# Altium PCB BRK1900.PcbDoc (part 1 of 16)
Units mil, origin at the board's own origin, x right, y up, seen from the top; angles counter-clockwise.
Board outline 8858.27 x 5905.51 mil, 10 copper layers (L1-TOP, L2-GND, L3-PWR, L4-GND, L5-PWR, L6-PWR, L7-GND, L8-SIG, L9-GND, L10-BOT), stack 48.824 mil thick; 456 components, 571 nets, 2296 pads, 2416 vias.
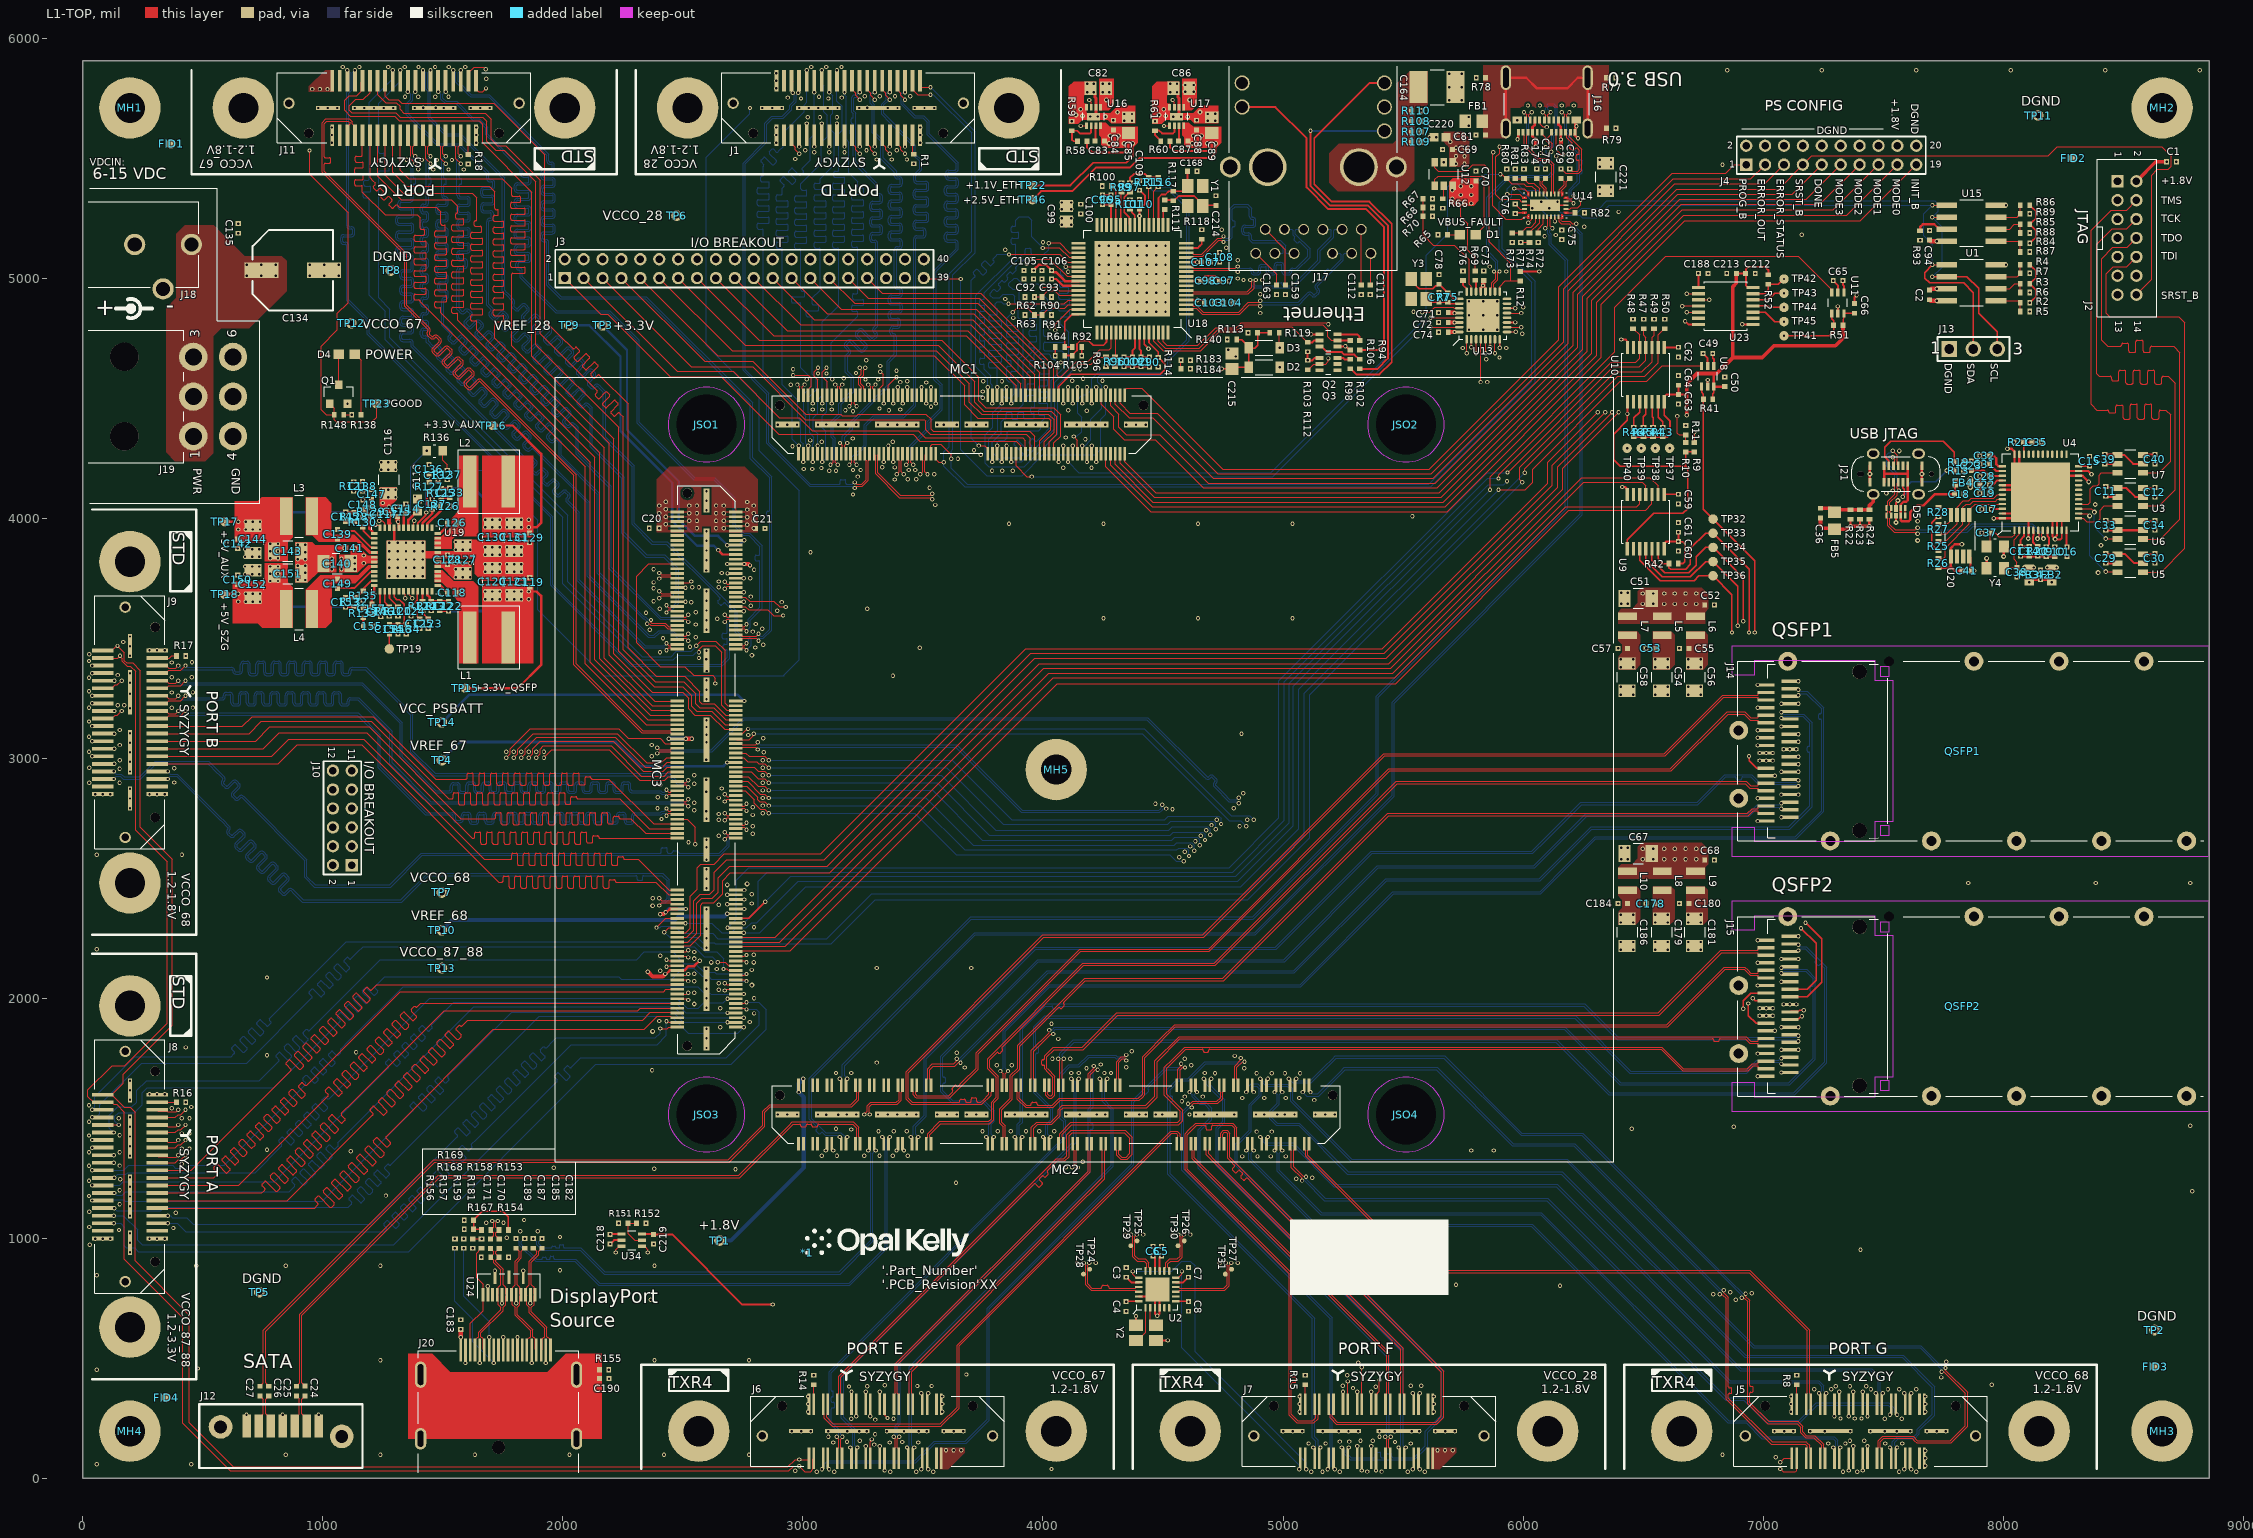
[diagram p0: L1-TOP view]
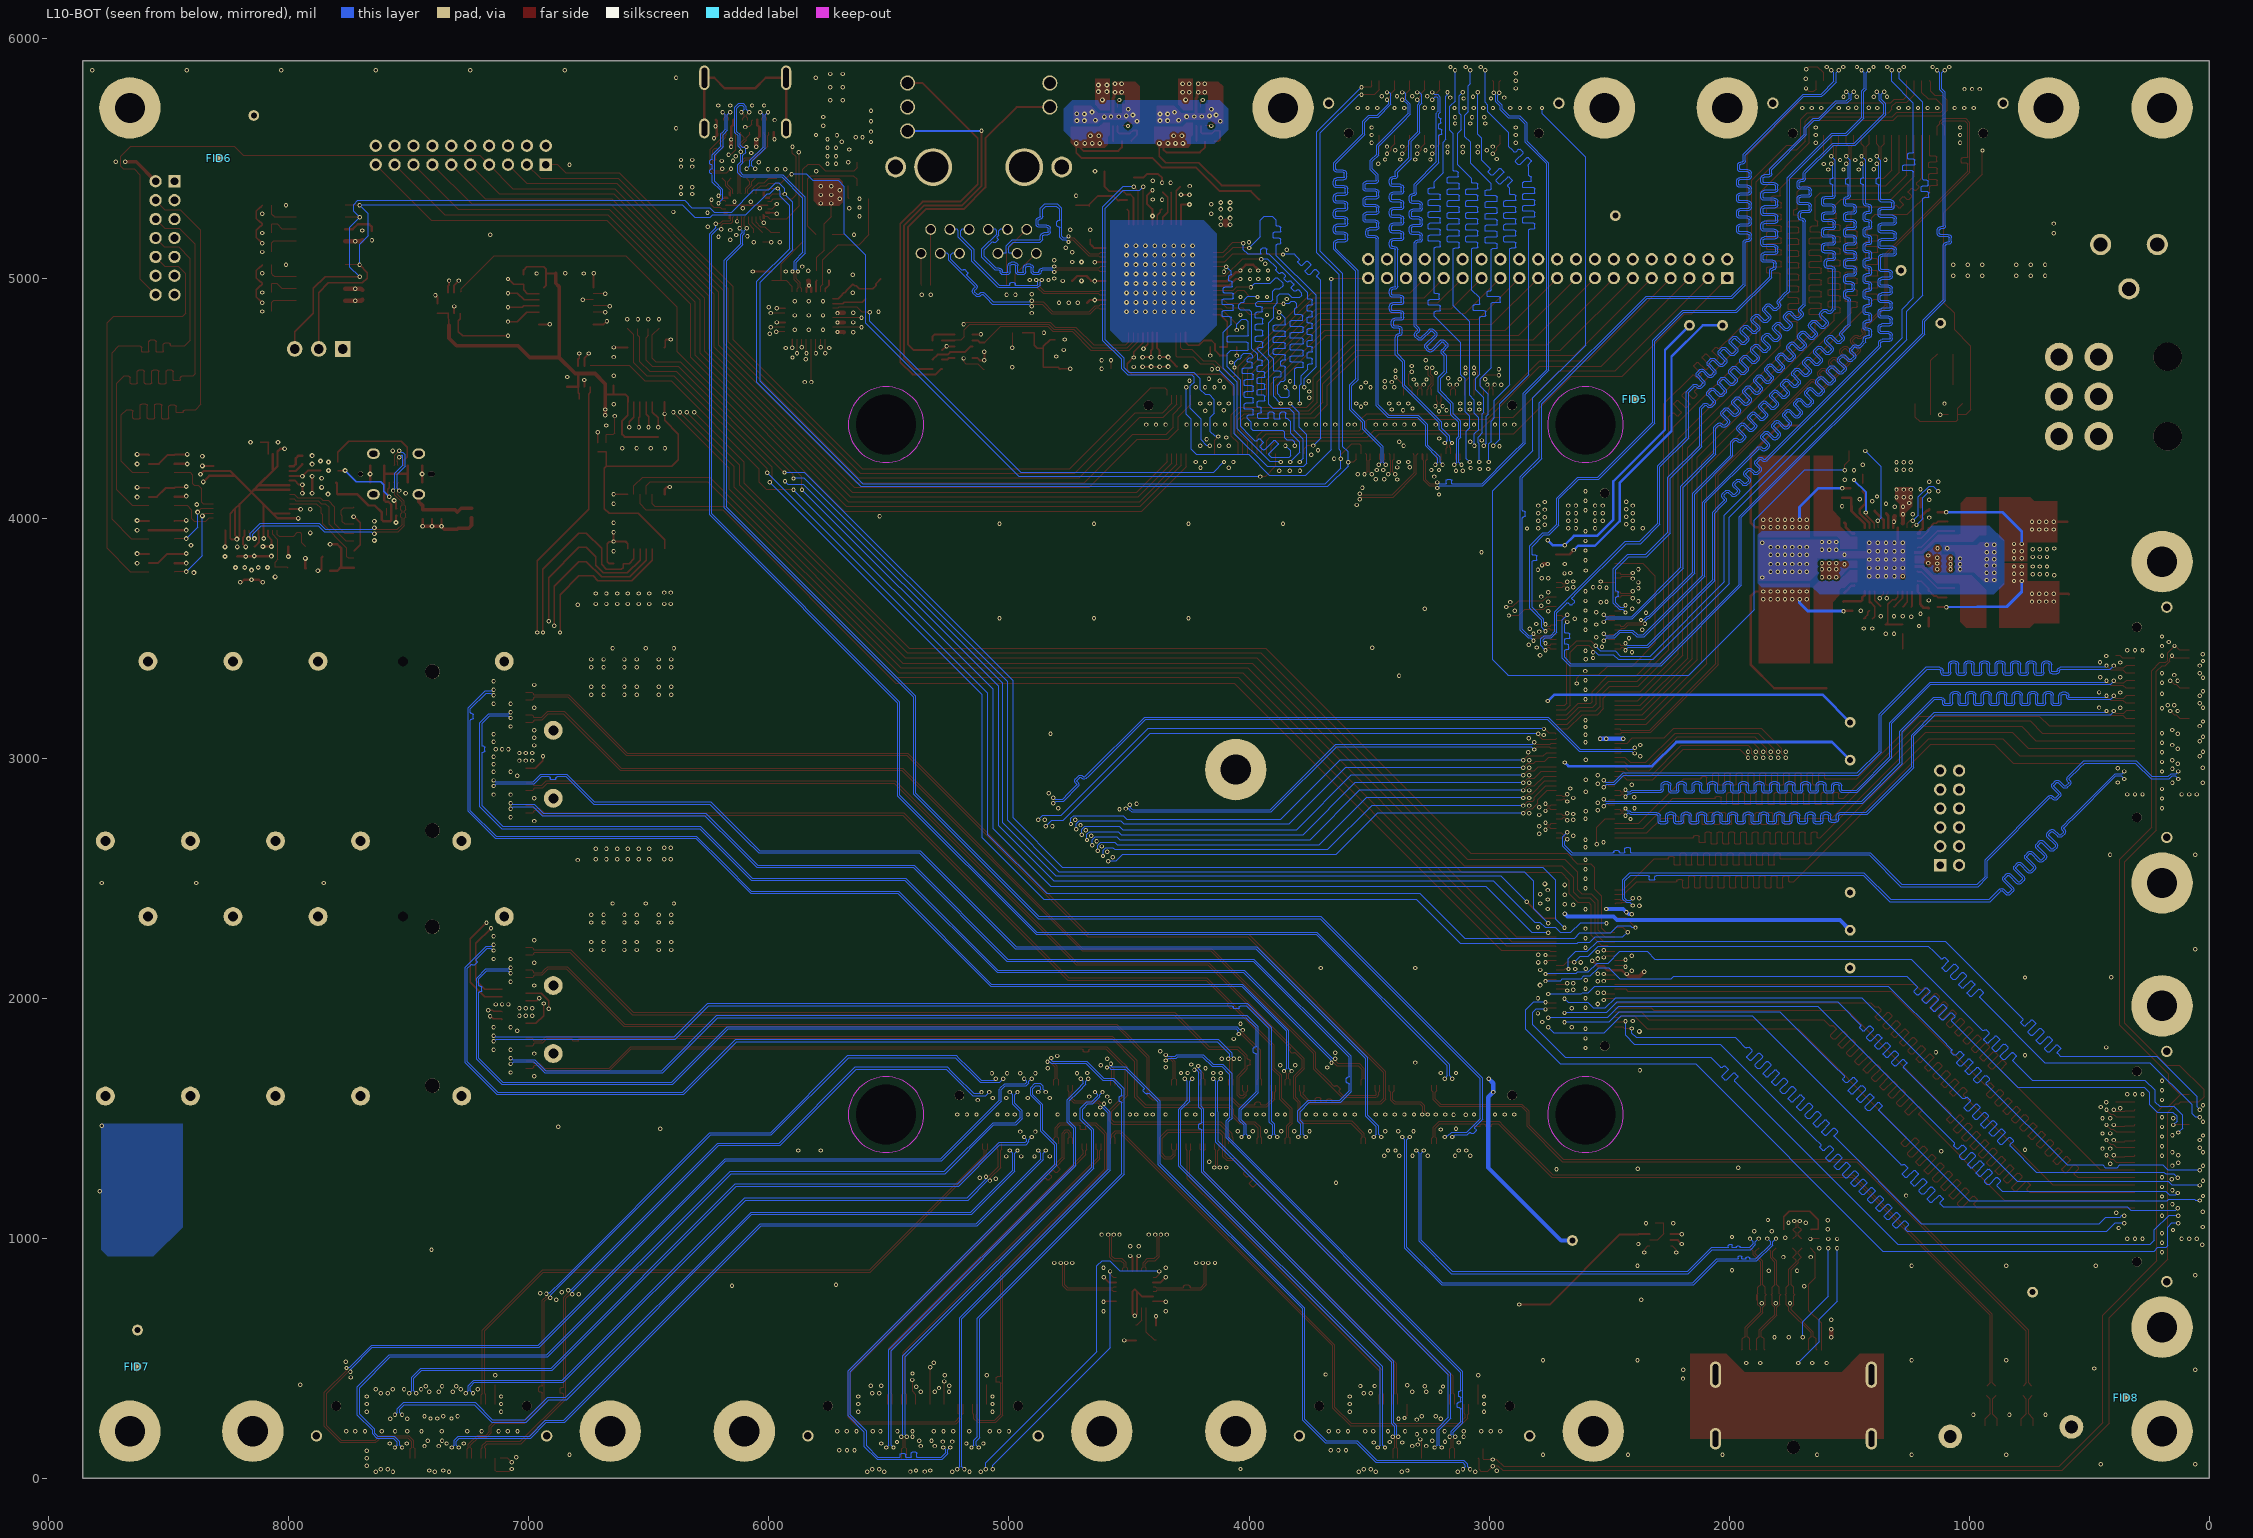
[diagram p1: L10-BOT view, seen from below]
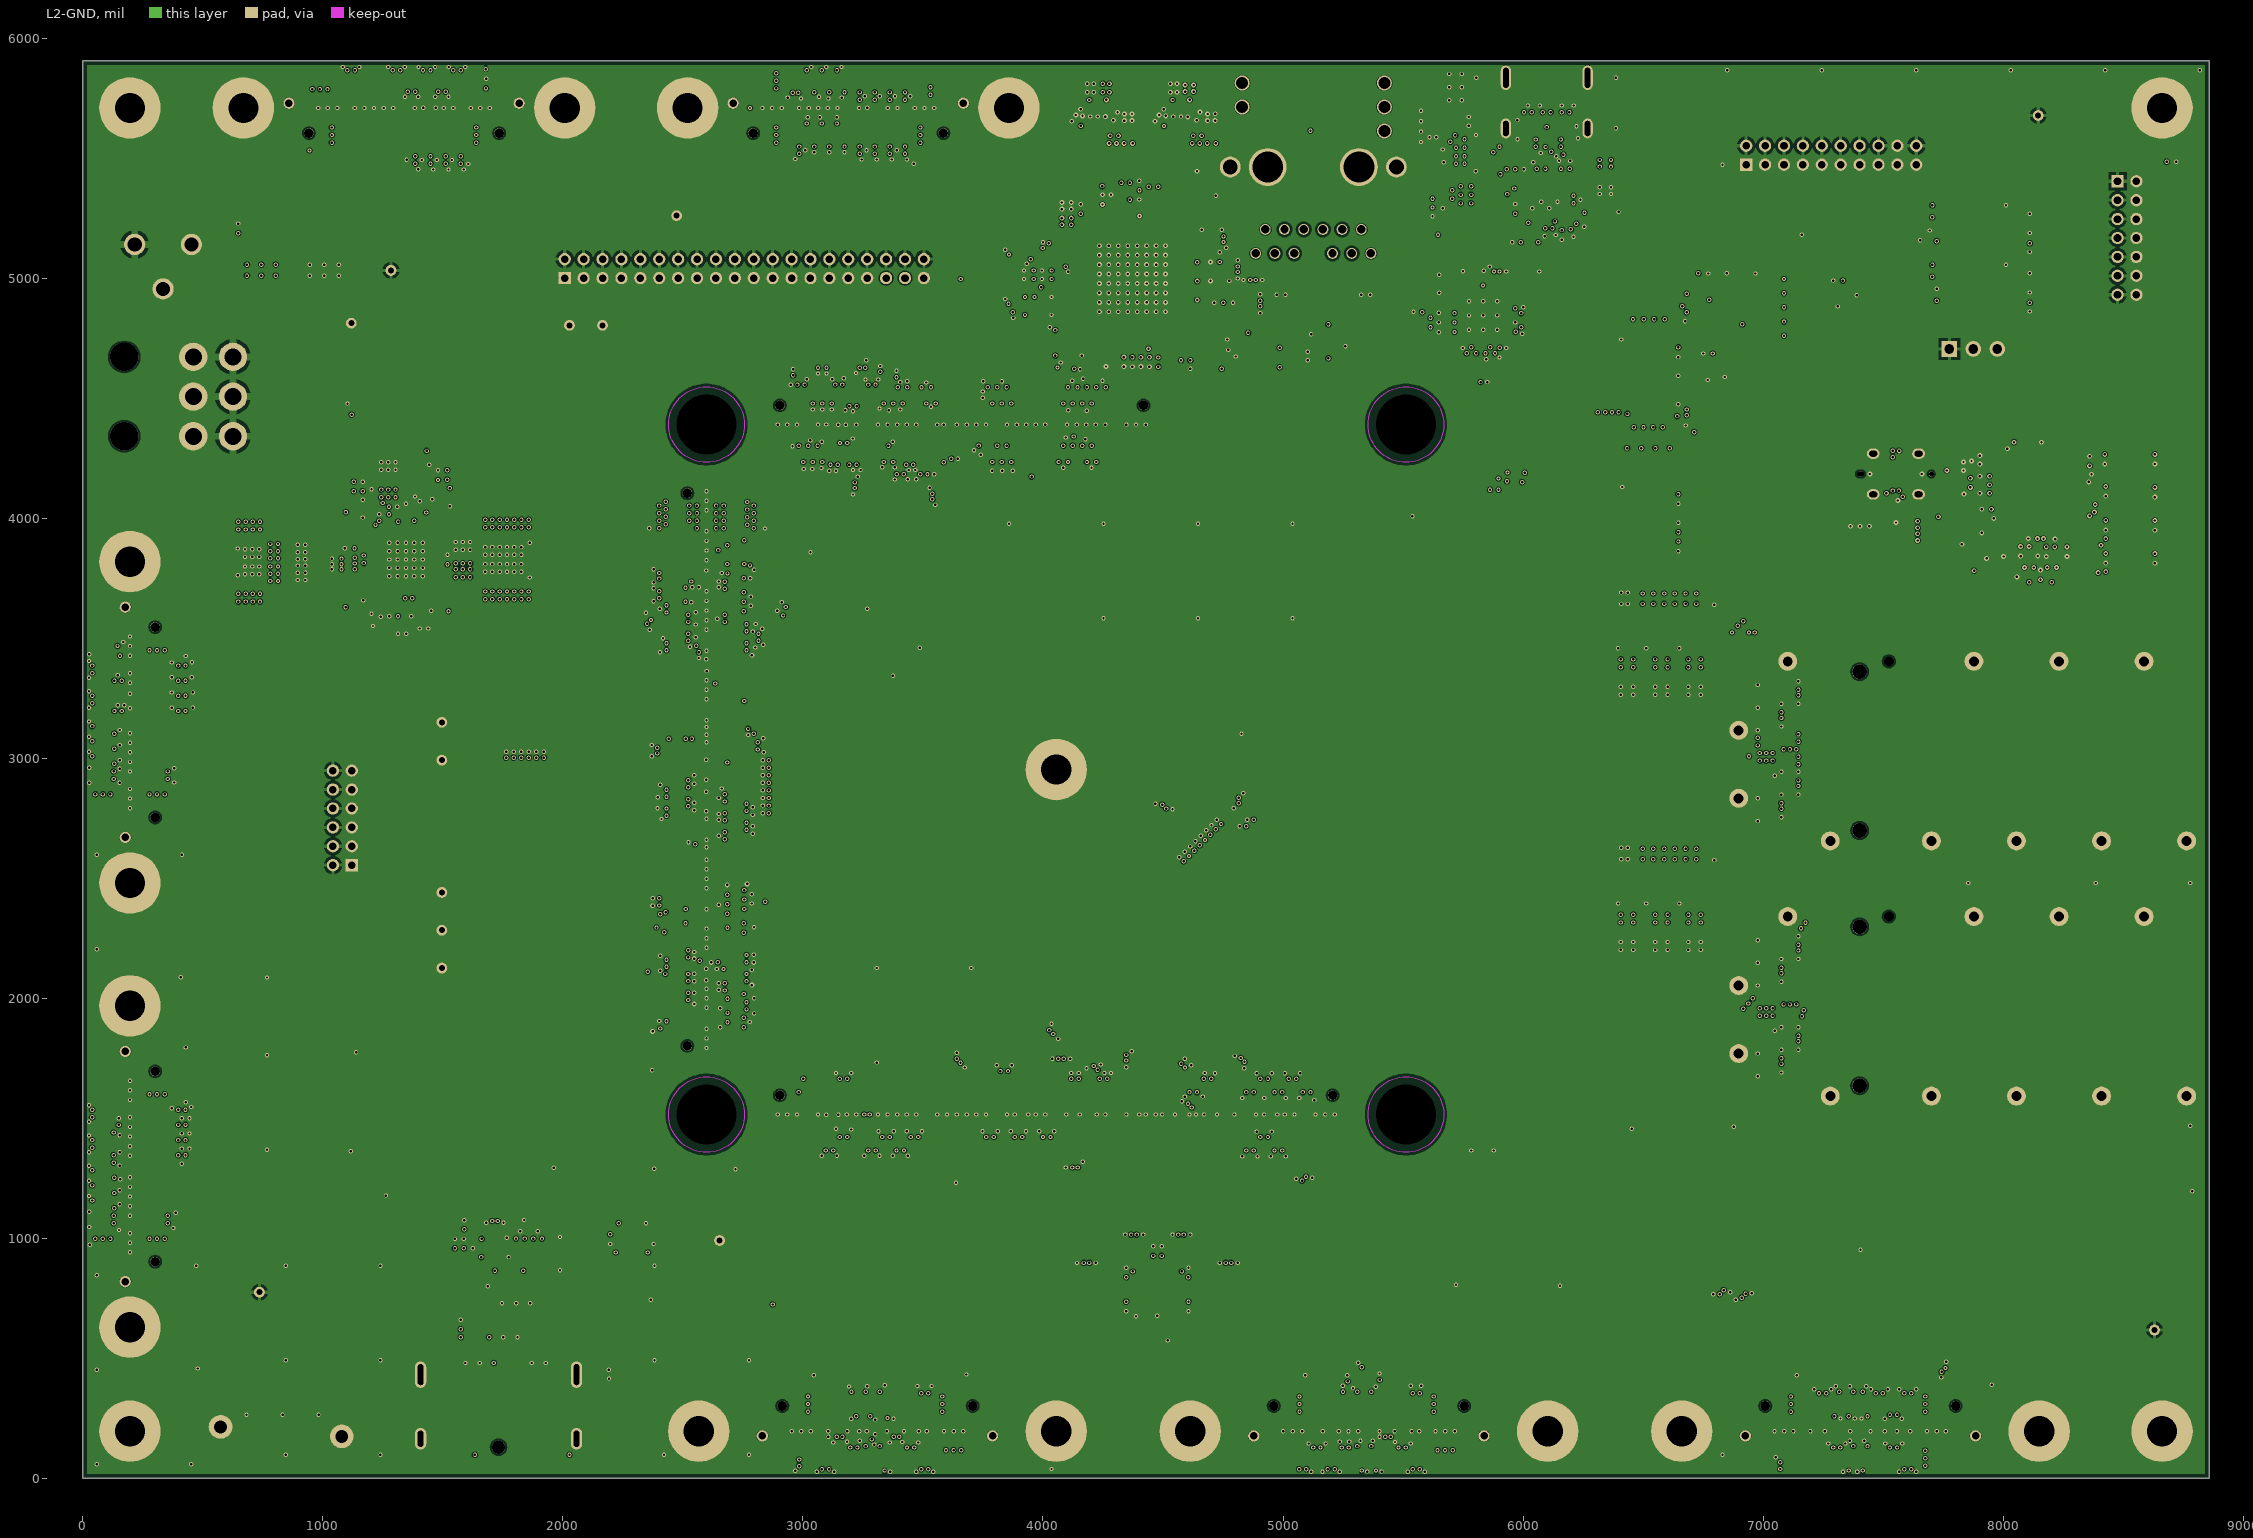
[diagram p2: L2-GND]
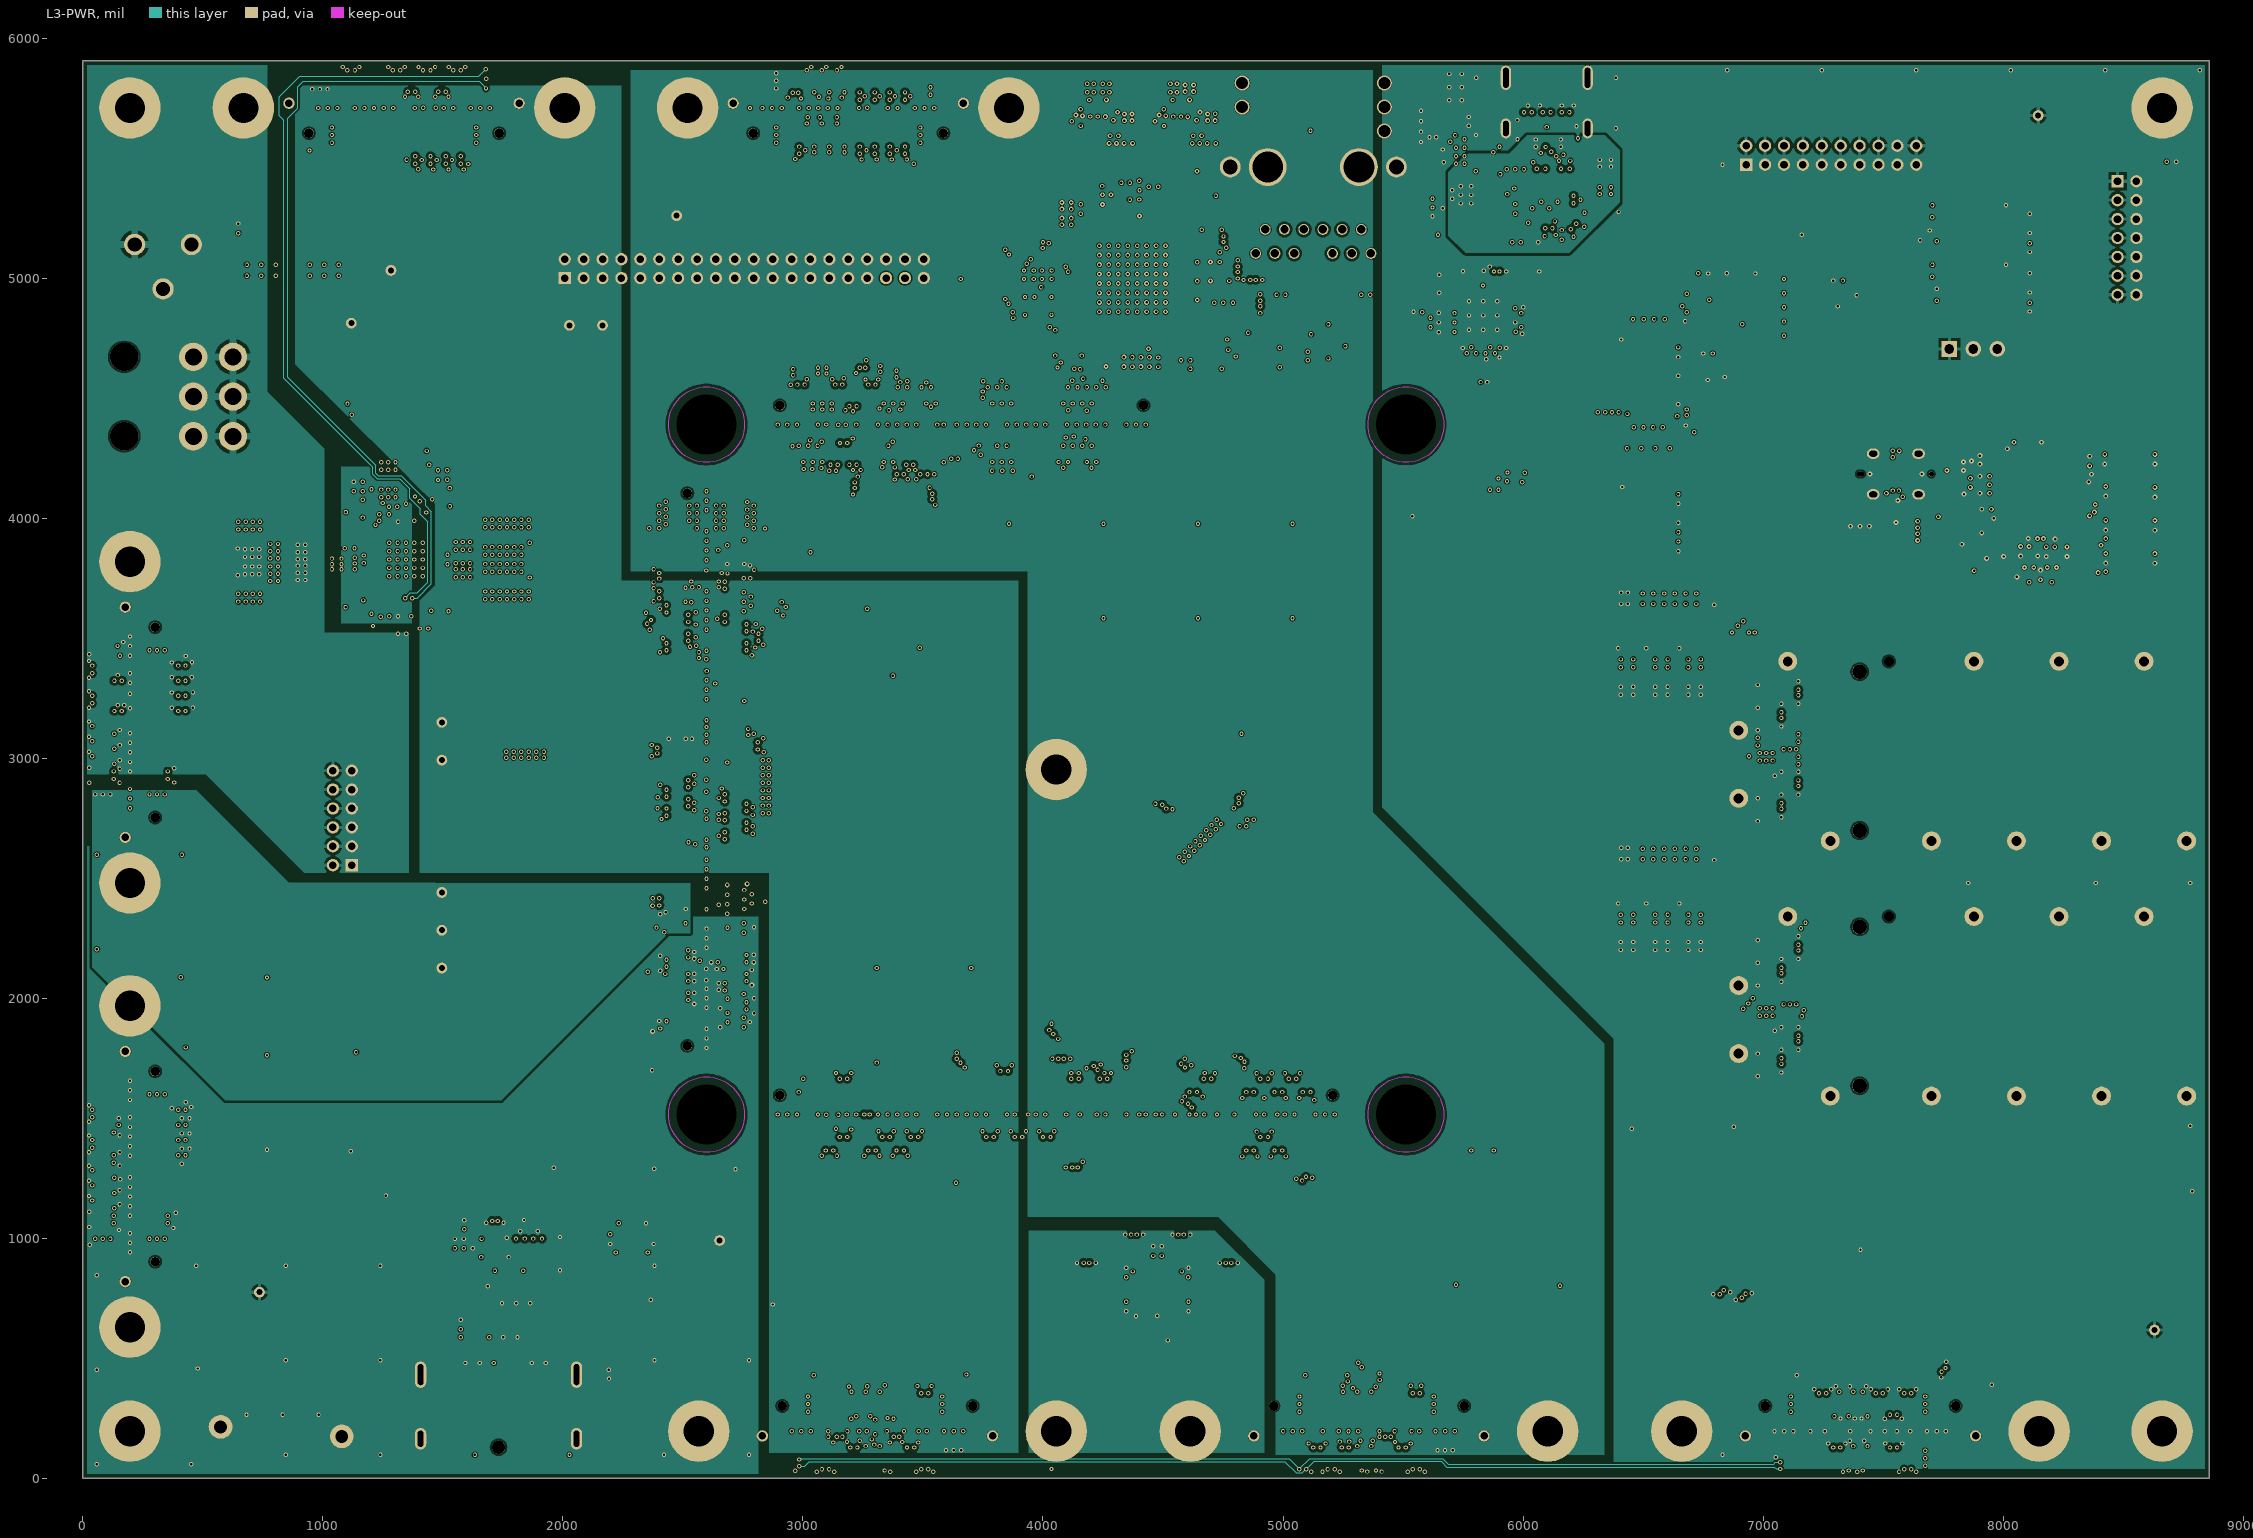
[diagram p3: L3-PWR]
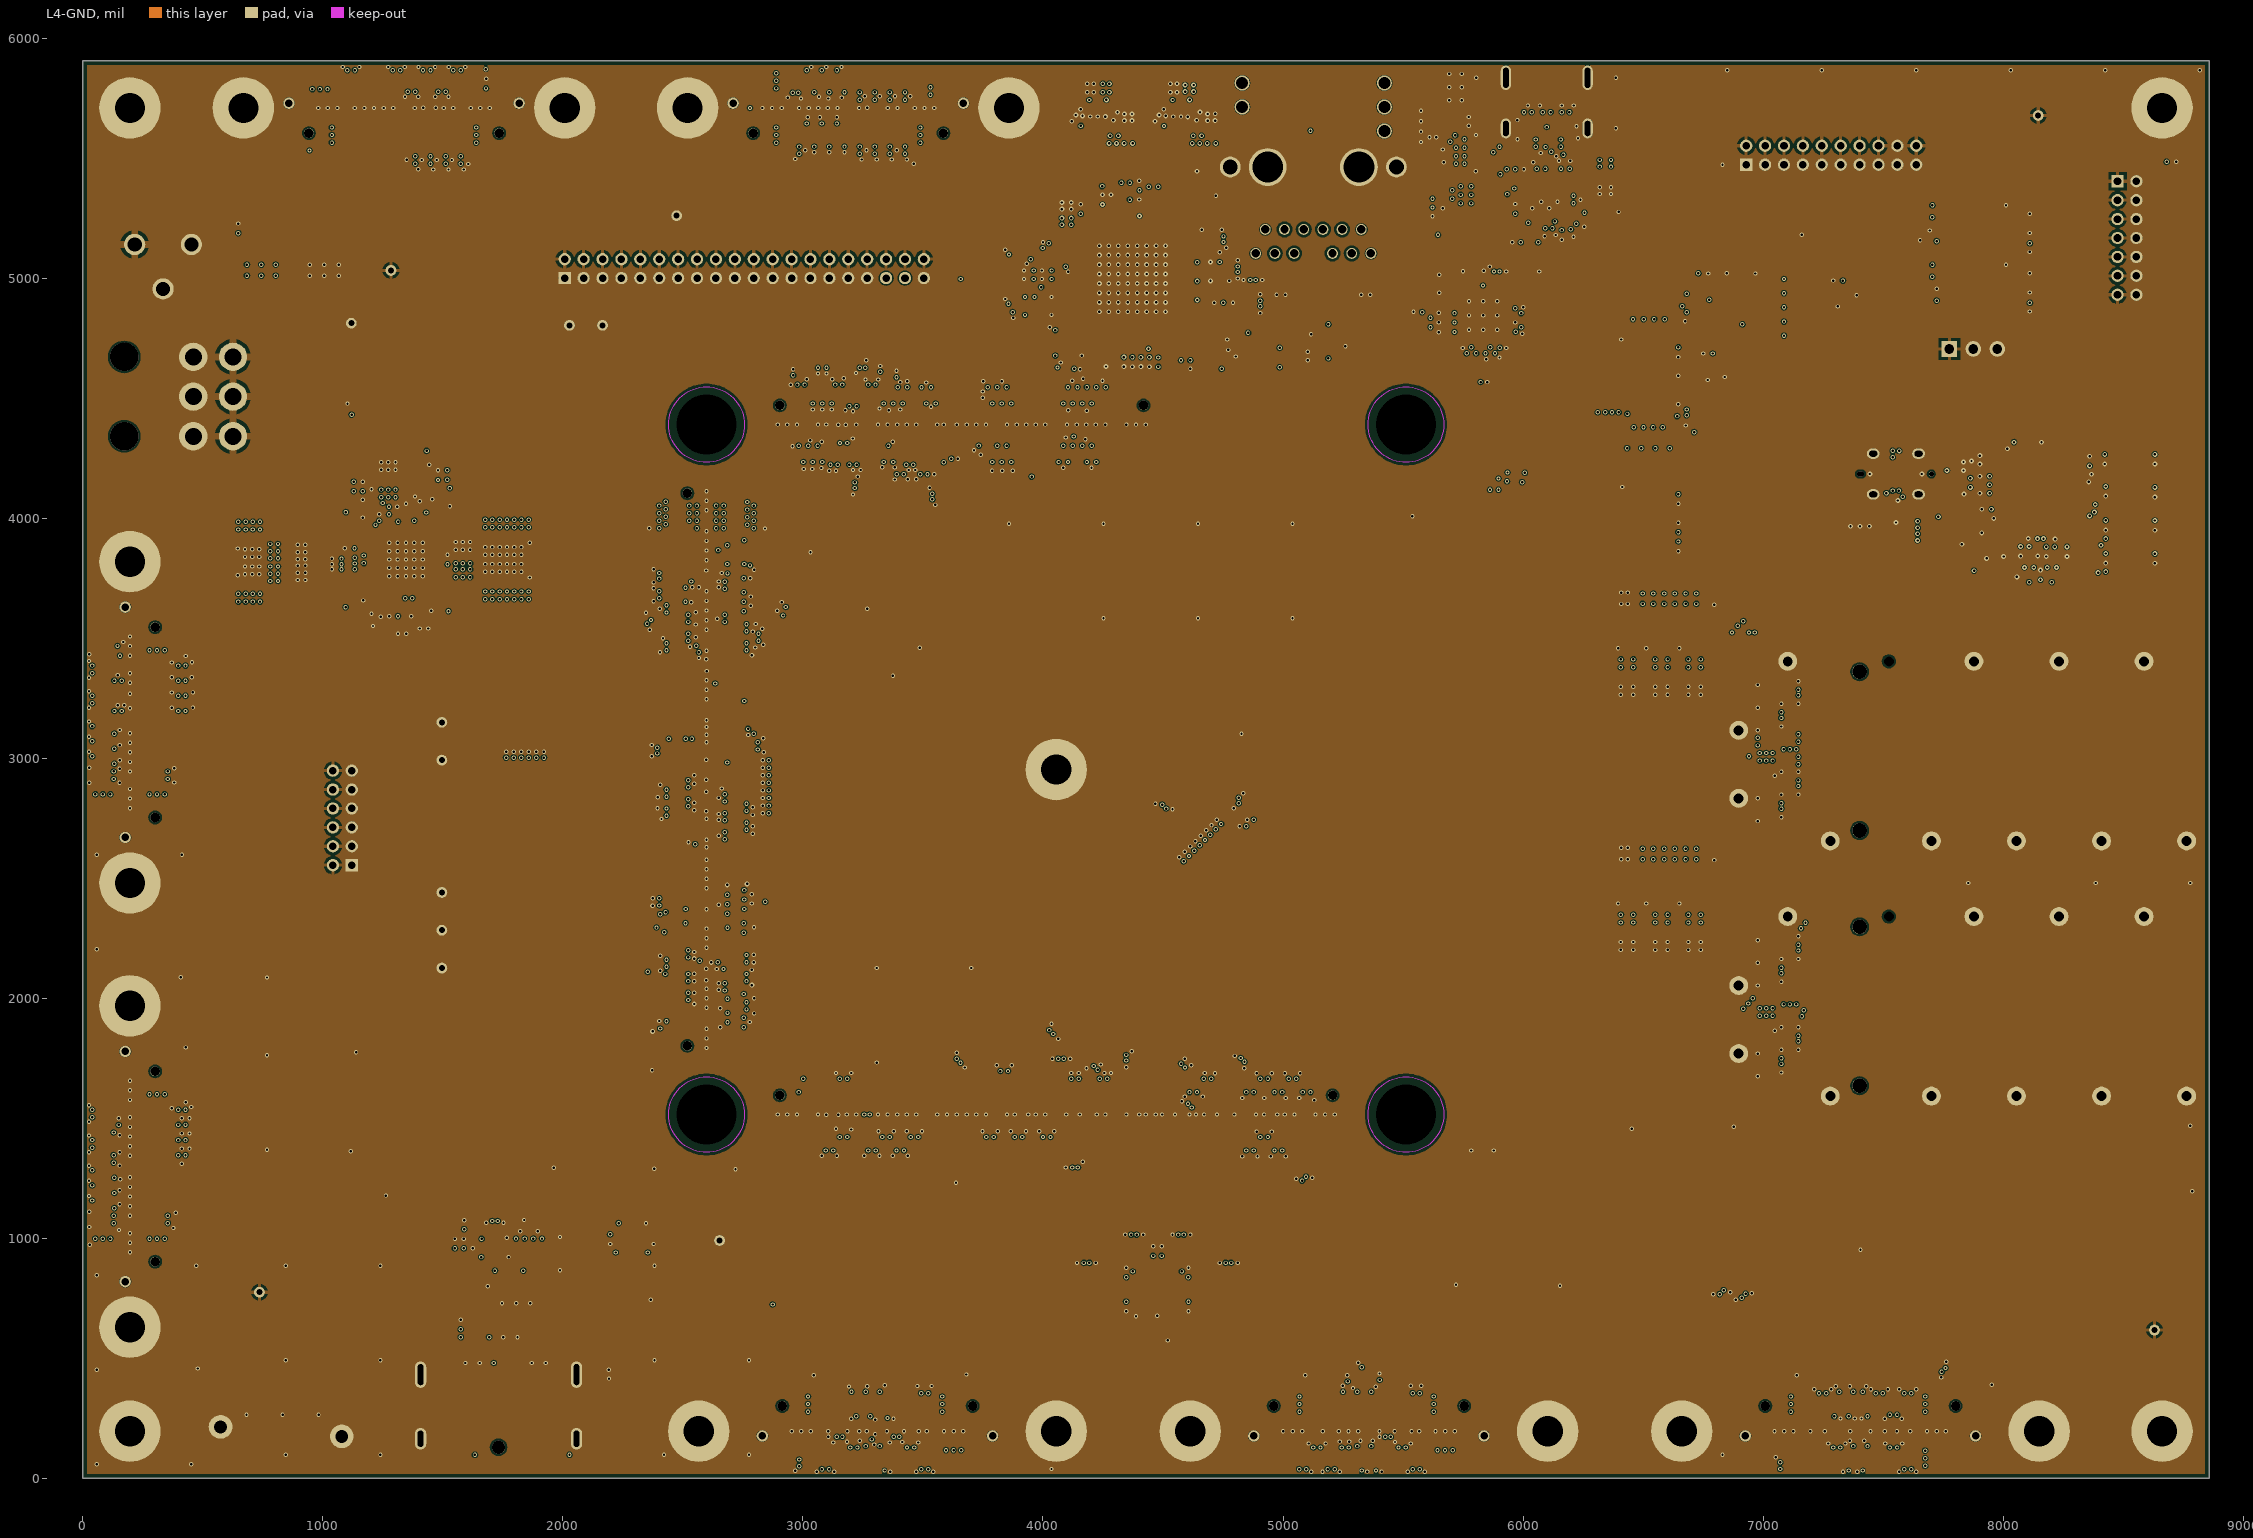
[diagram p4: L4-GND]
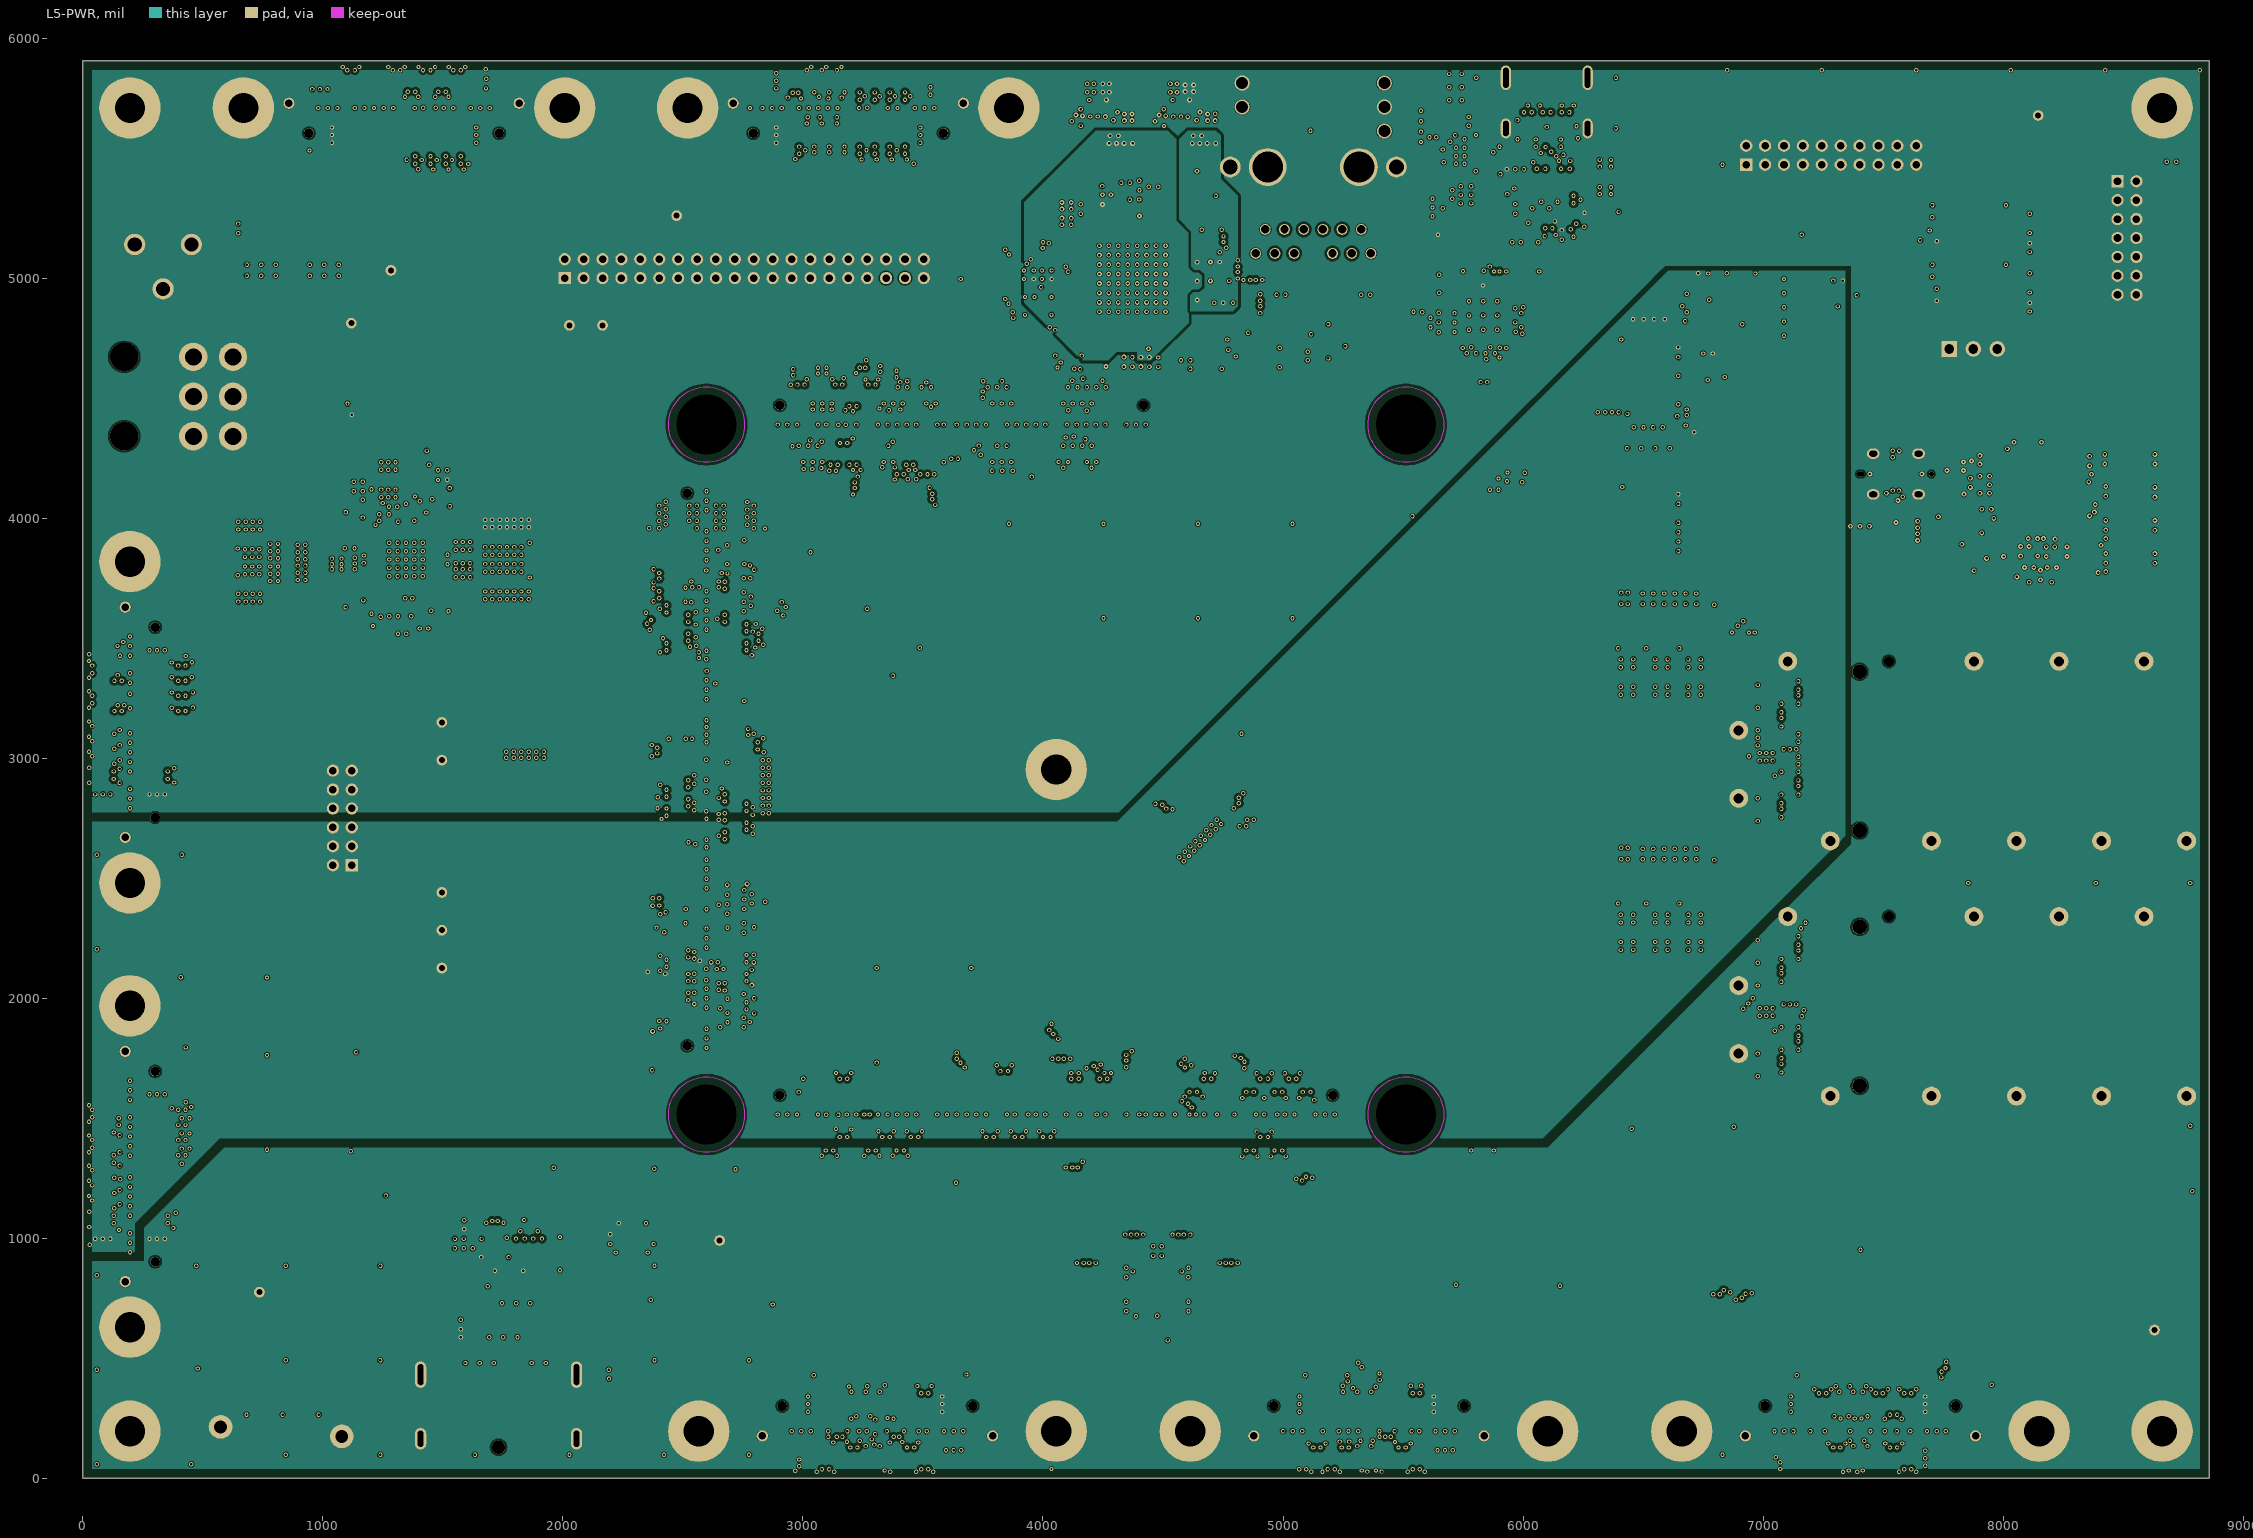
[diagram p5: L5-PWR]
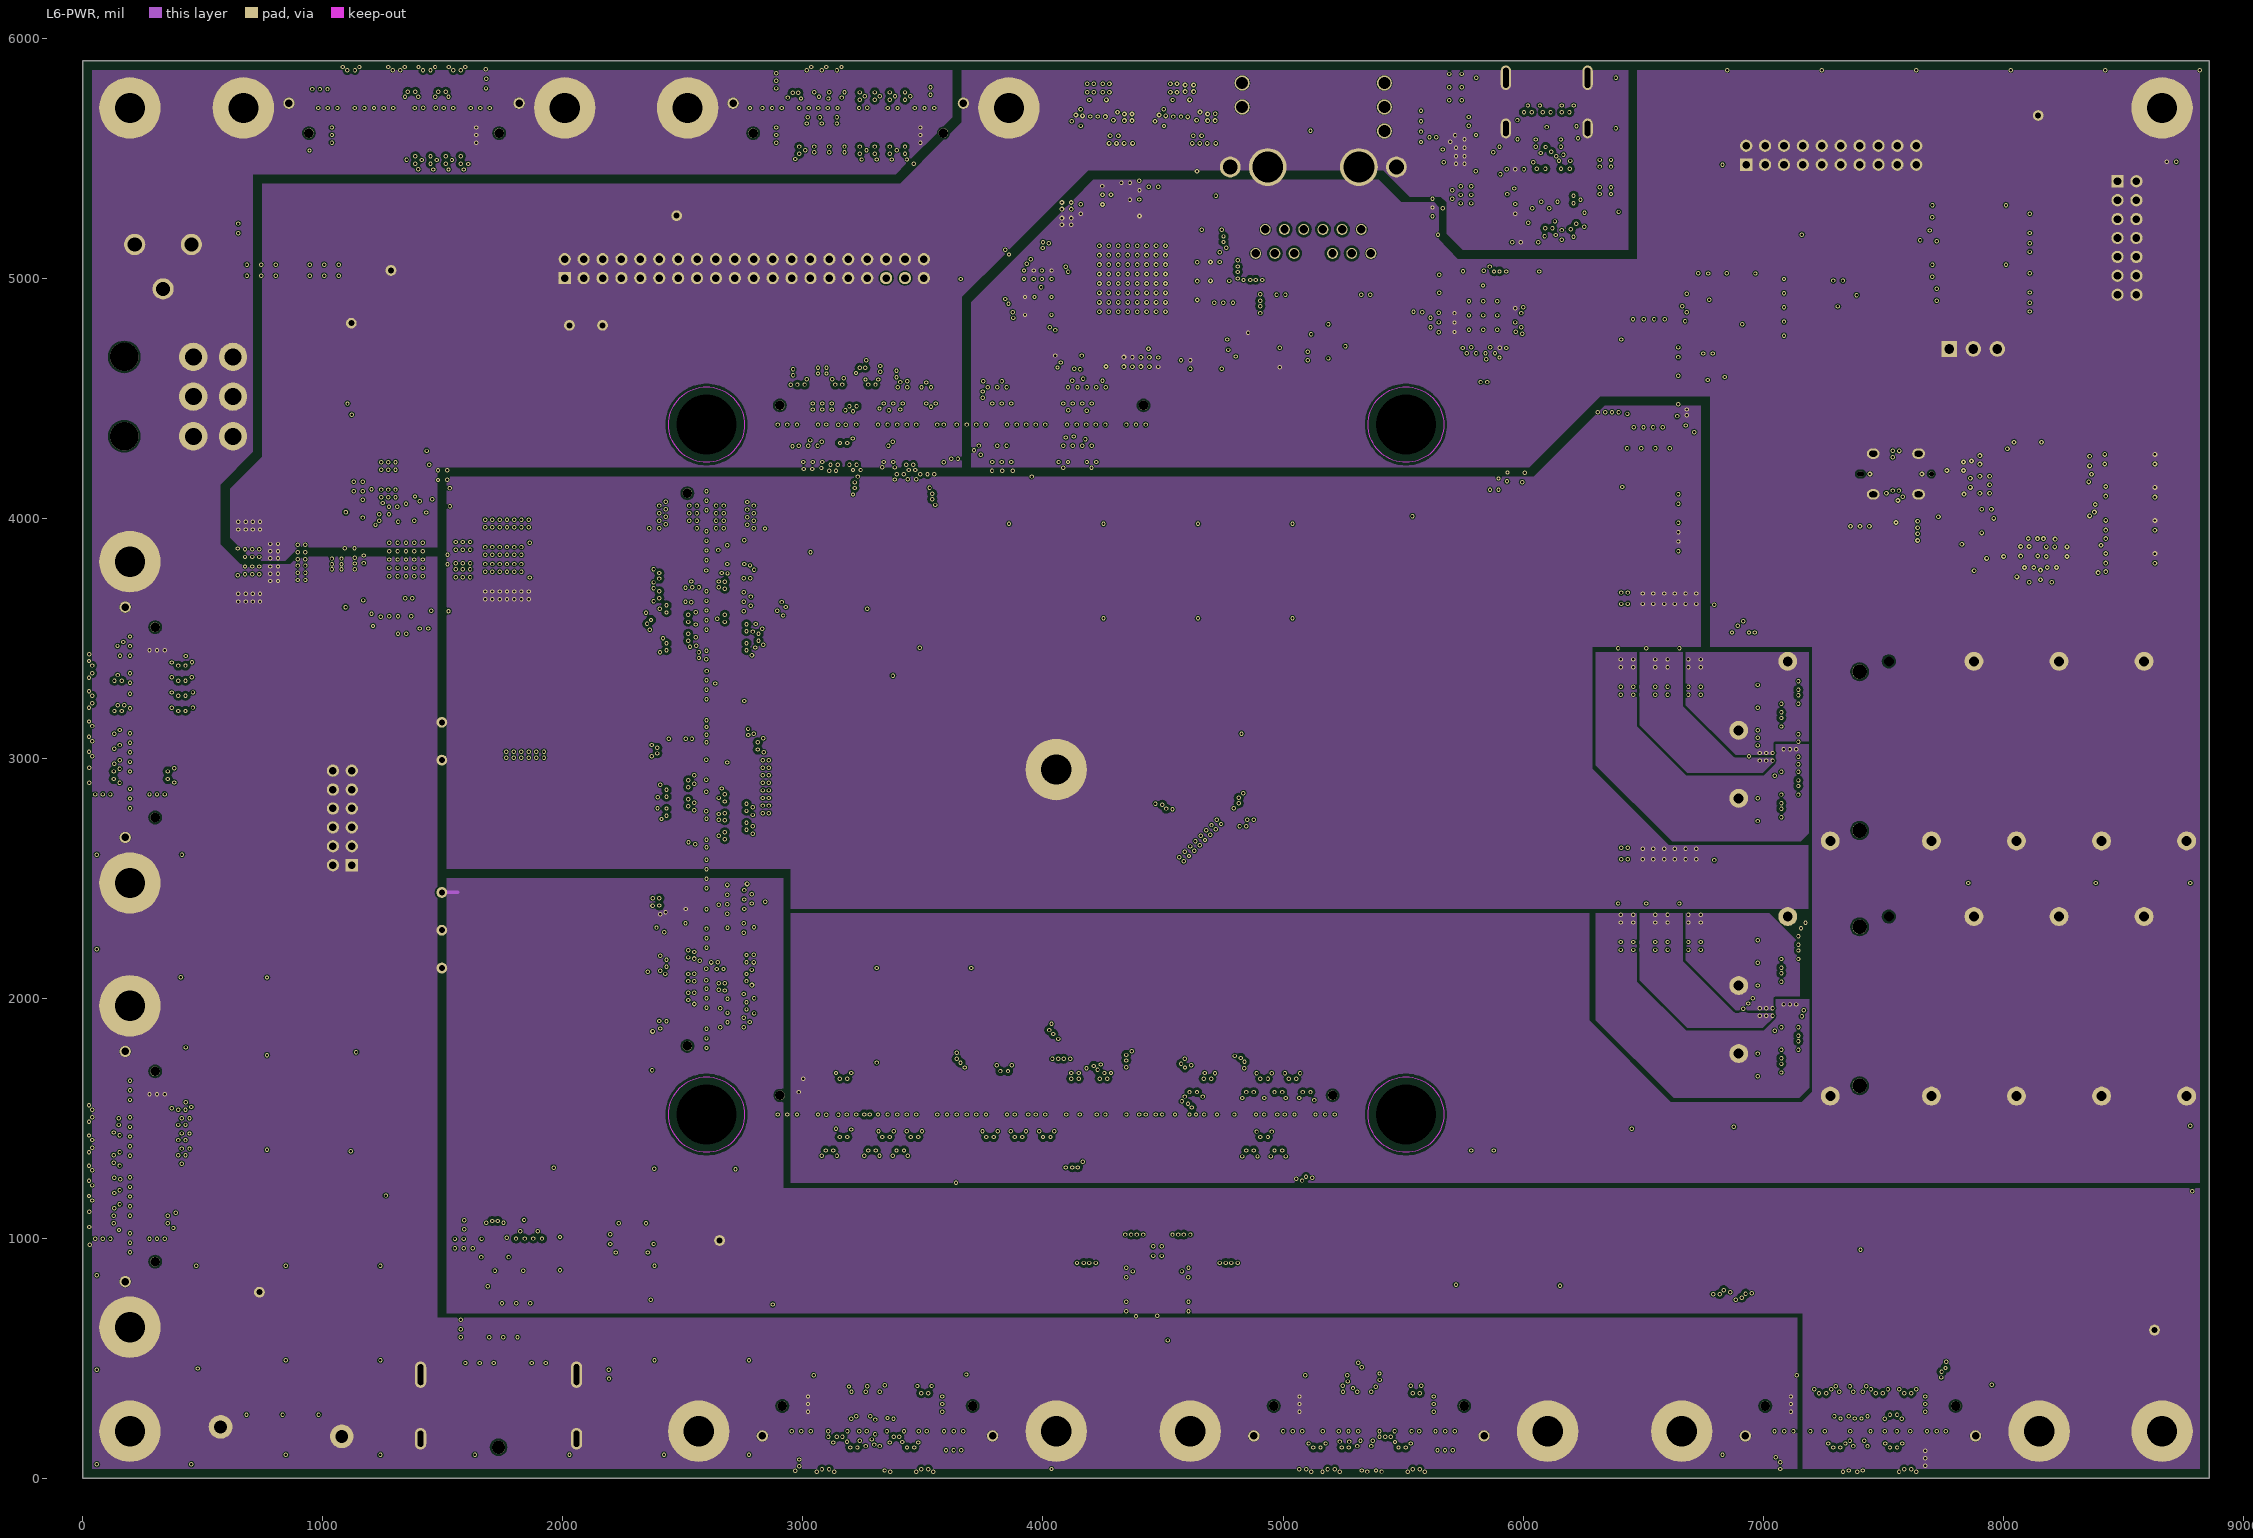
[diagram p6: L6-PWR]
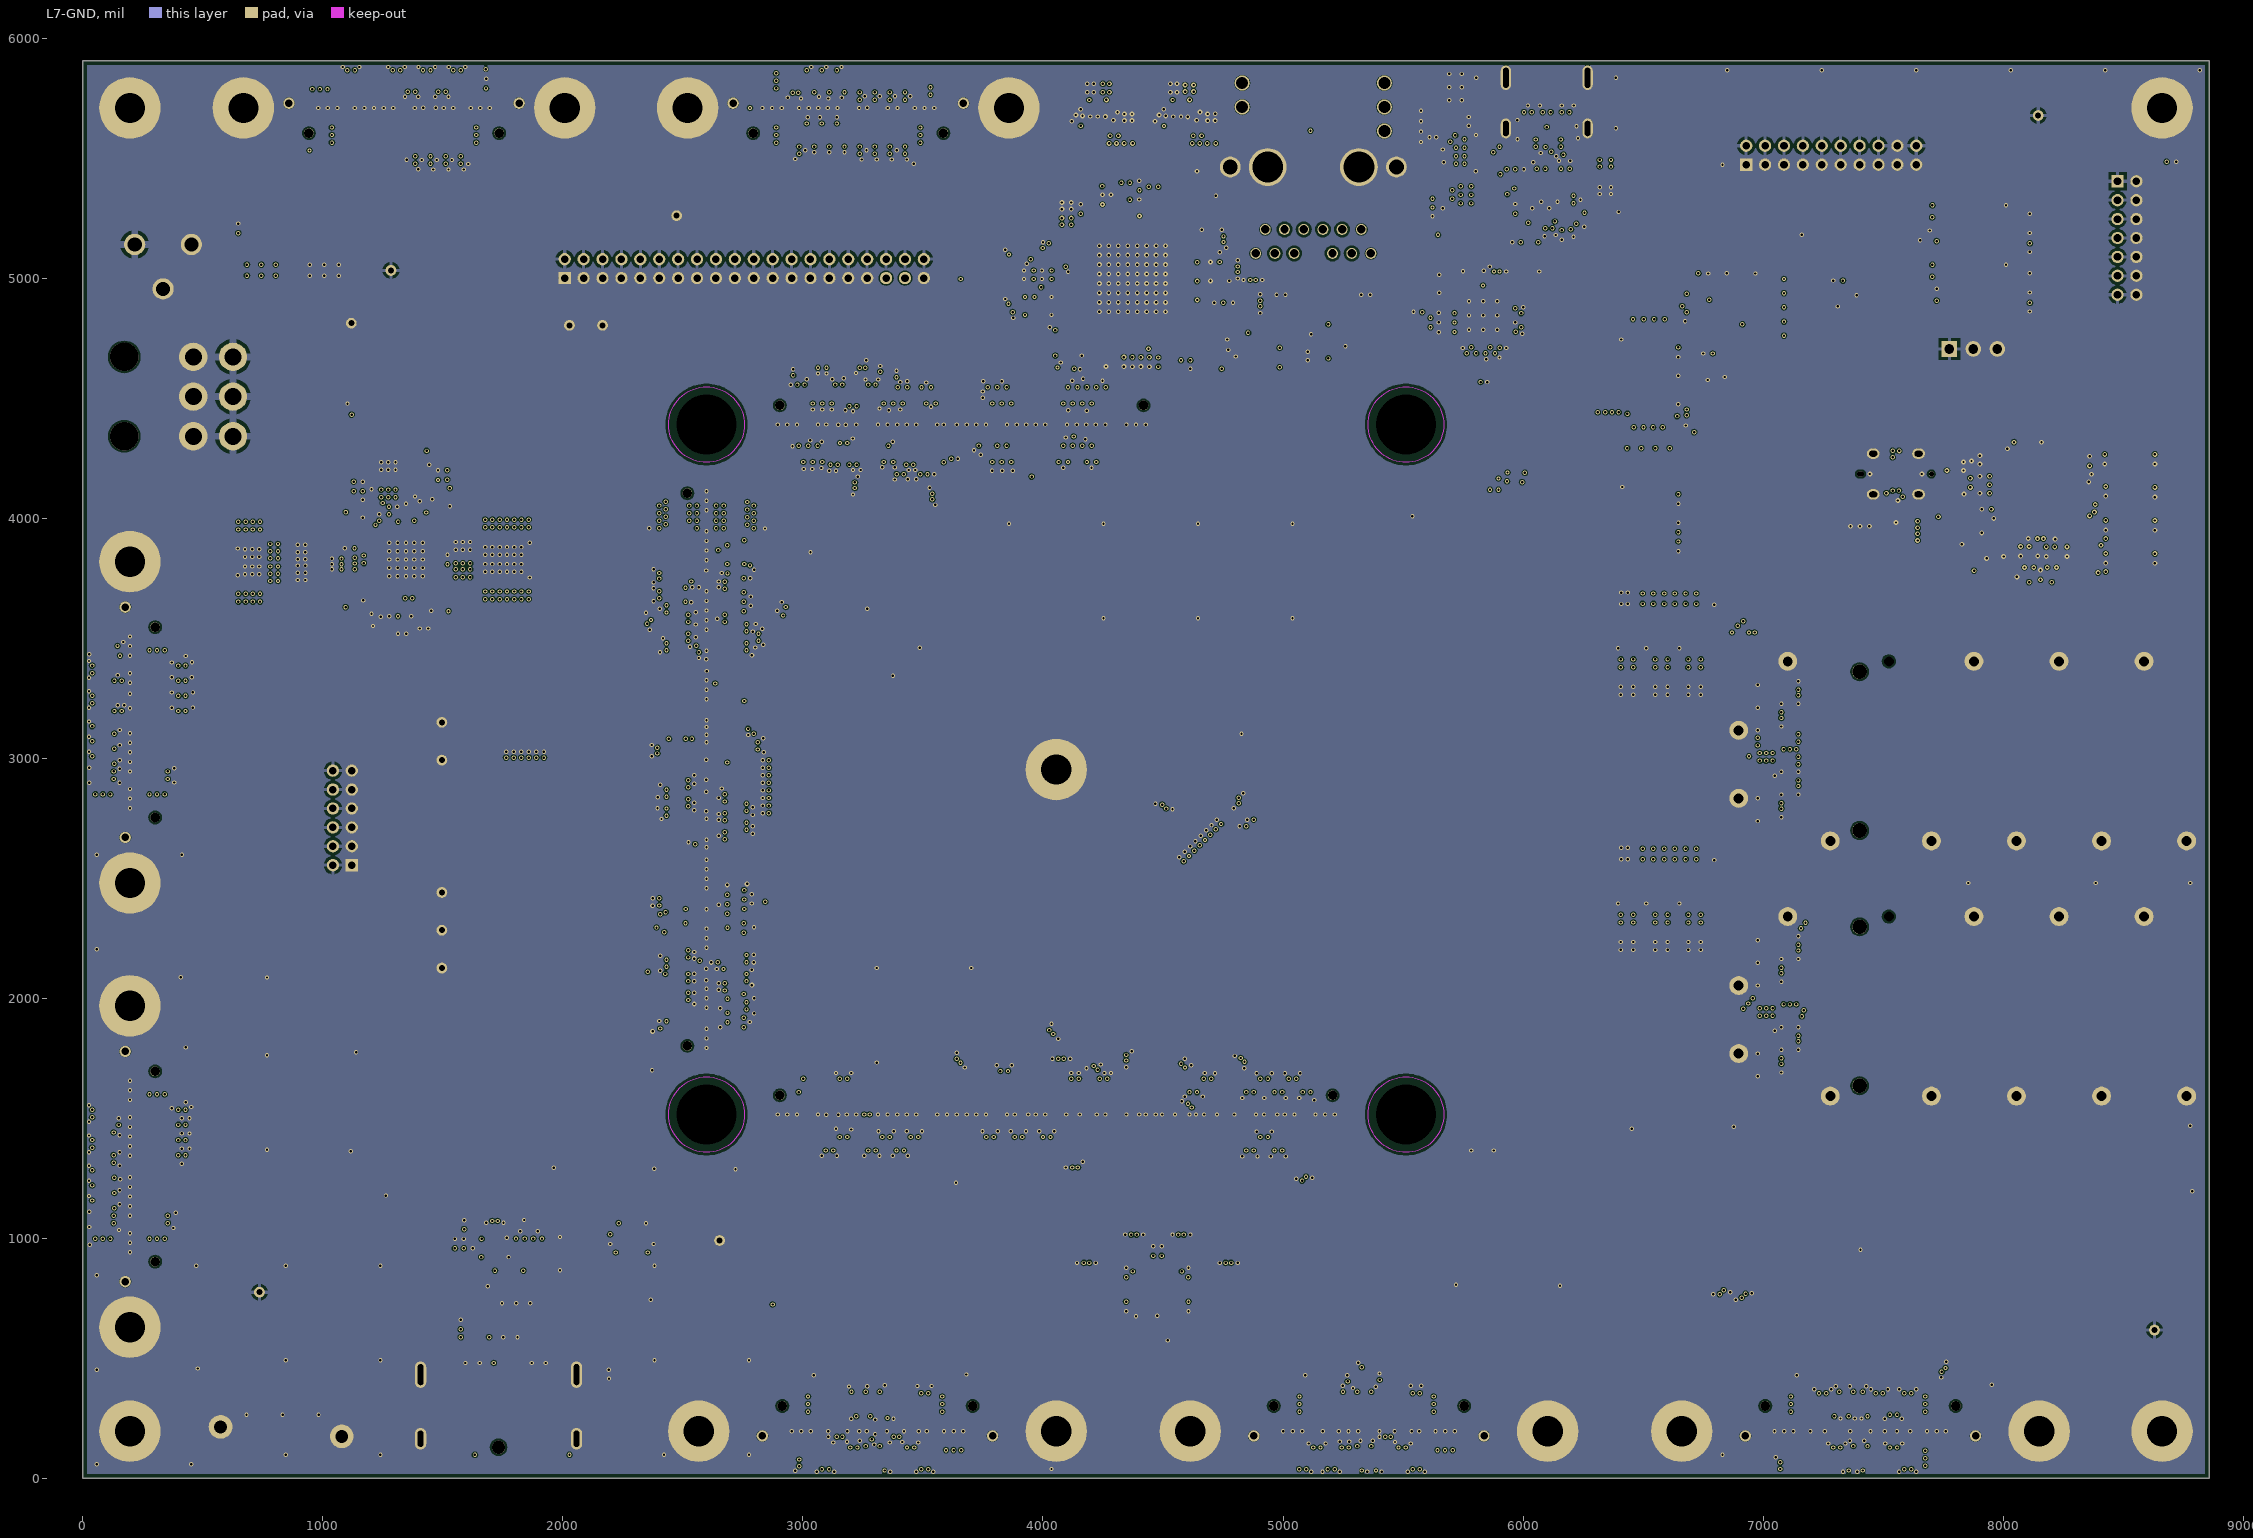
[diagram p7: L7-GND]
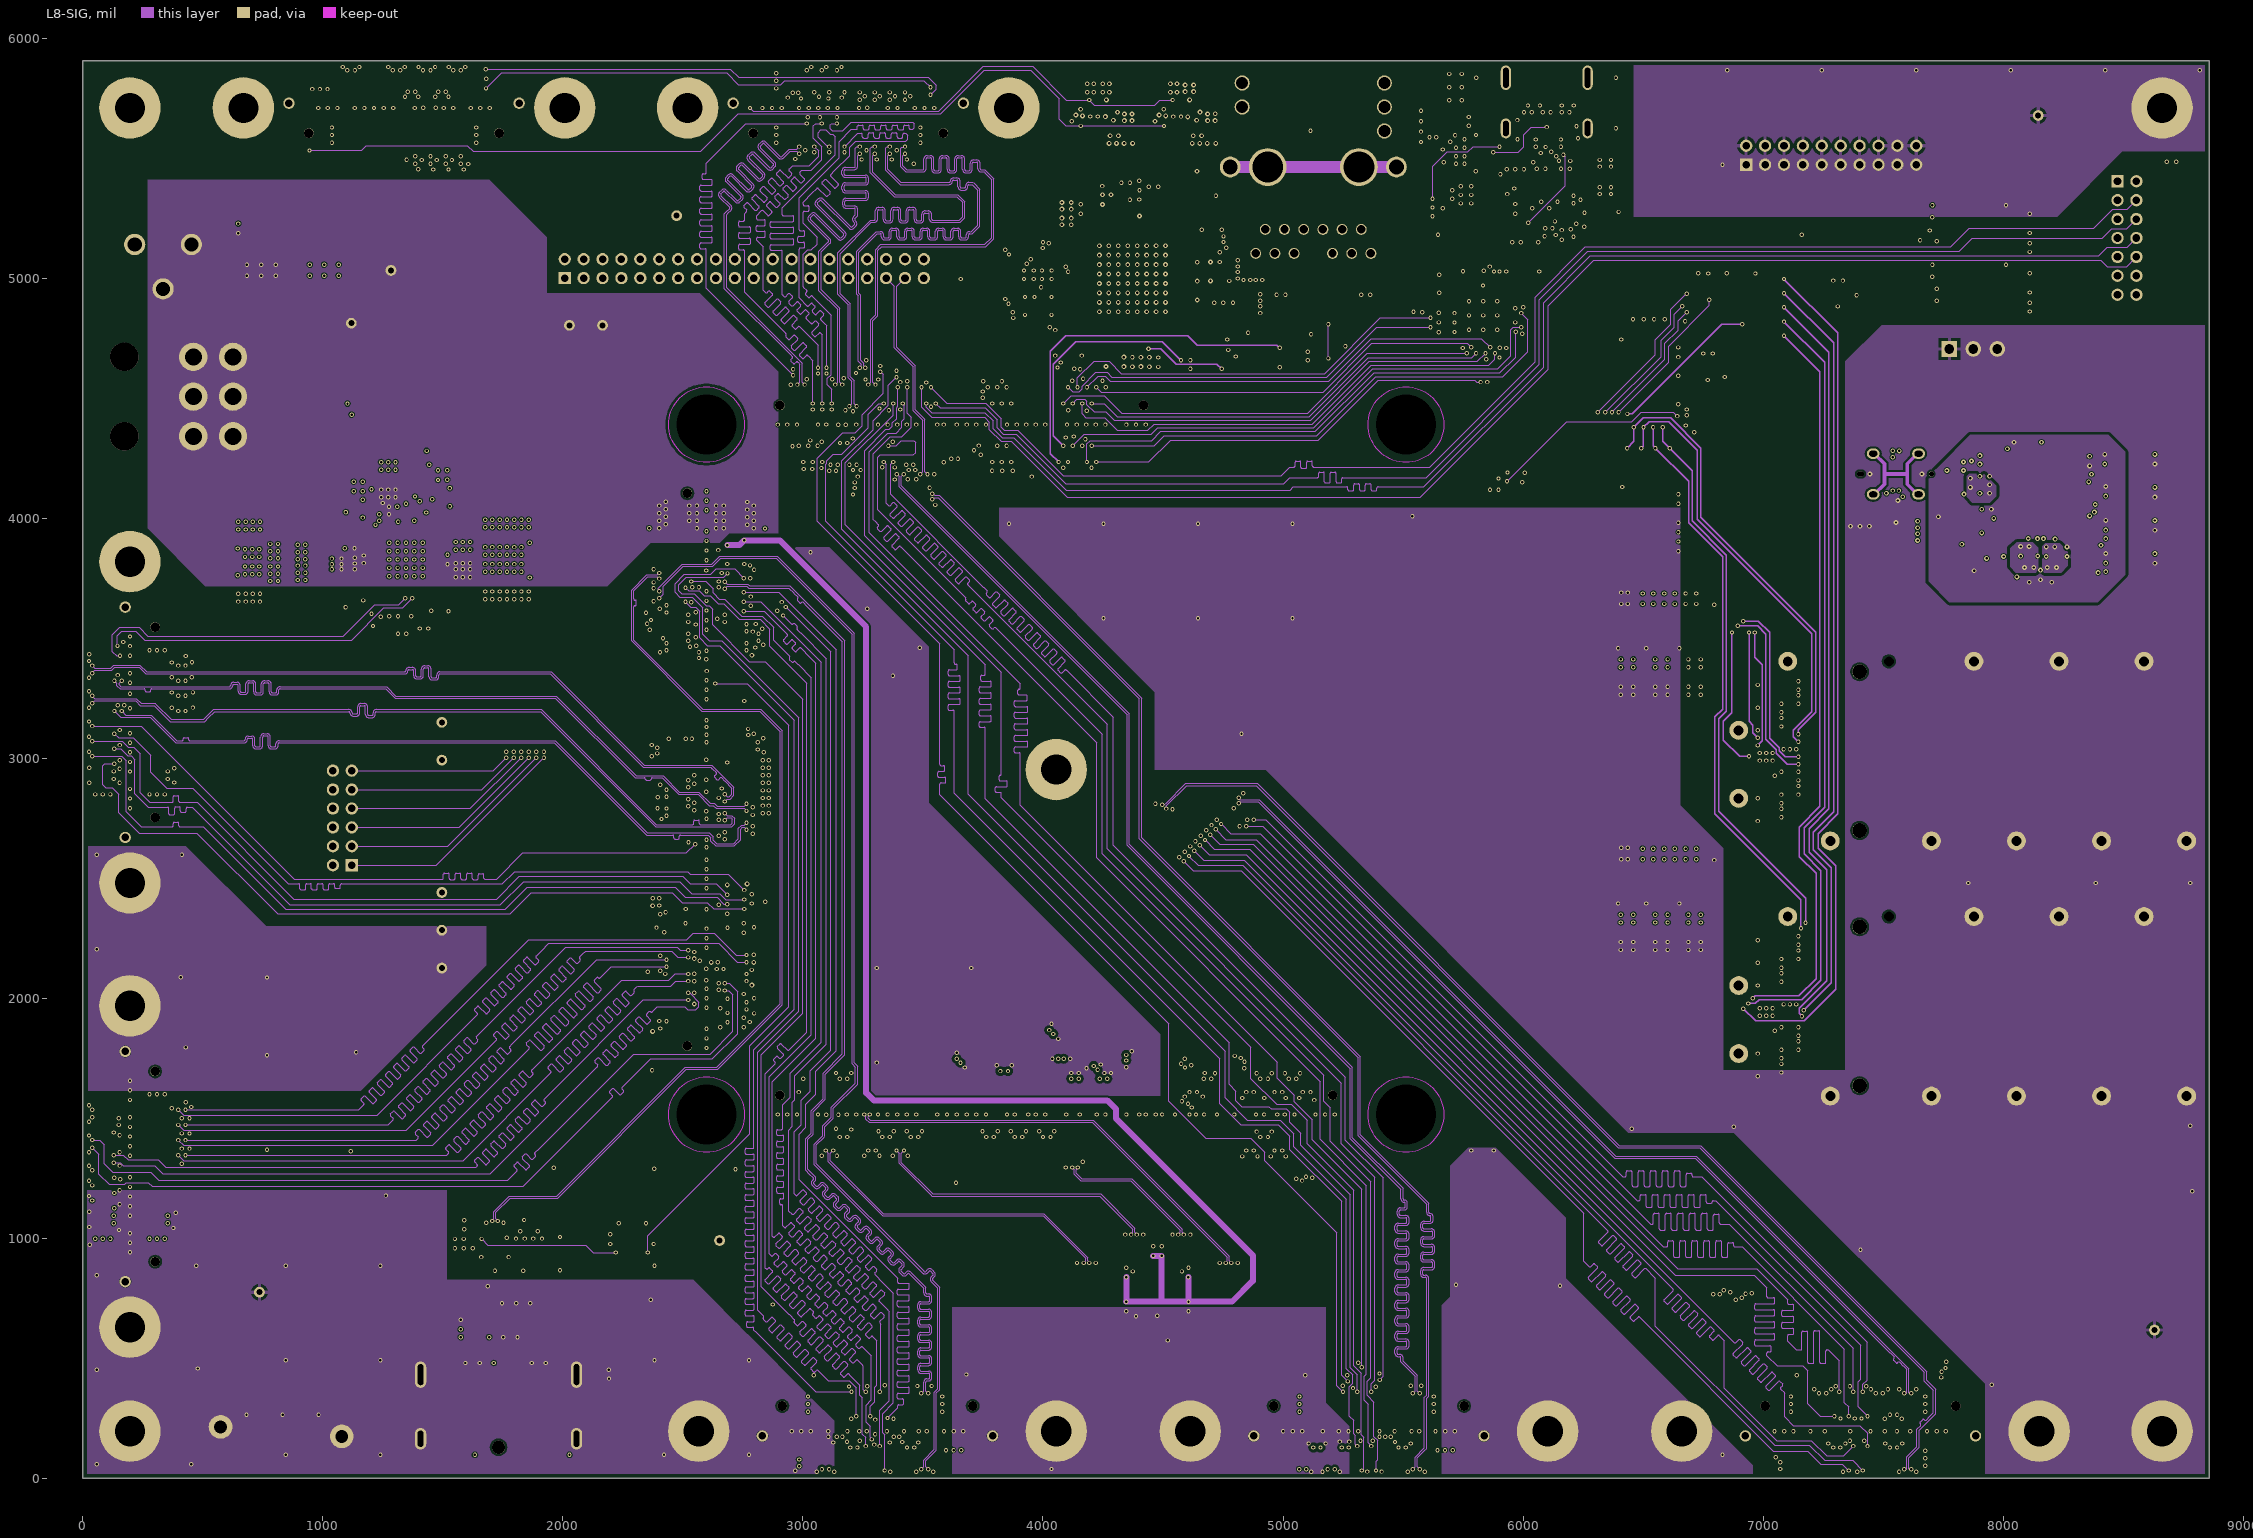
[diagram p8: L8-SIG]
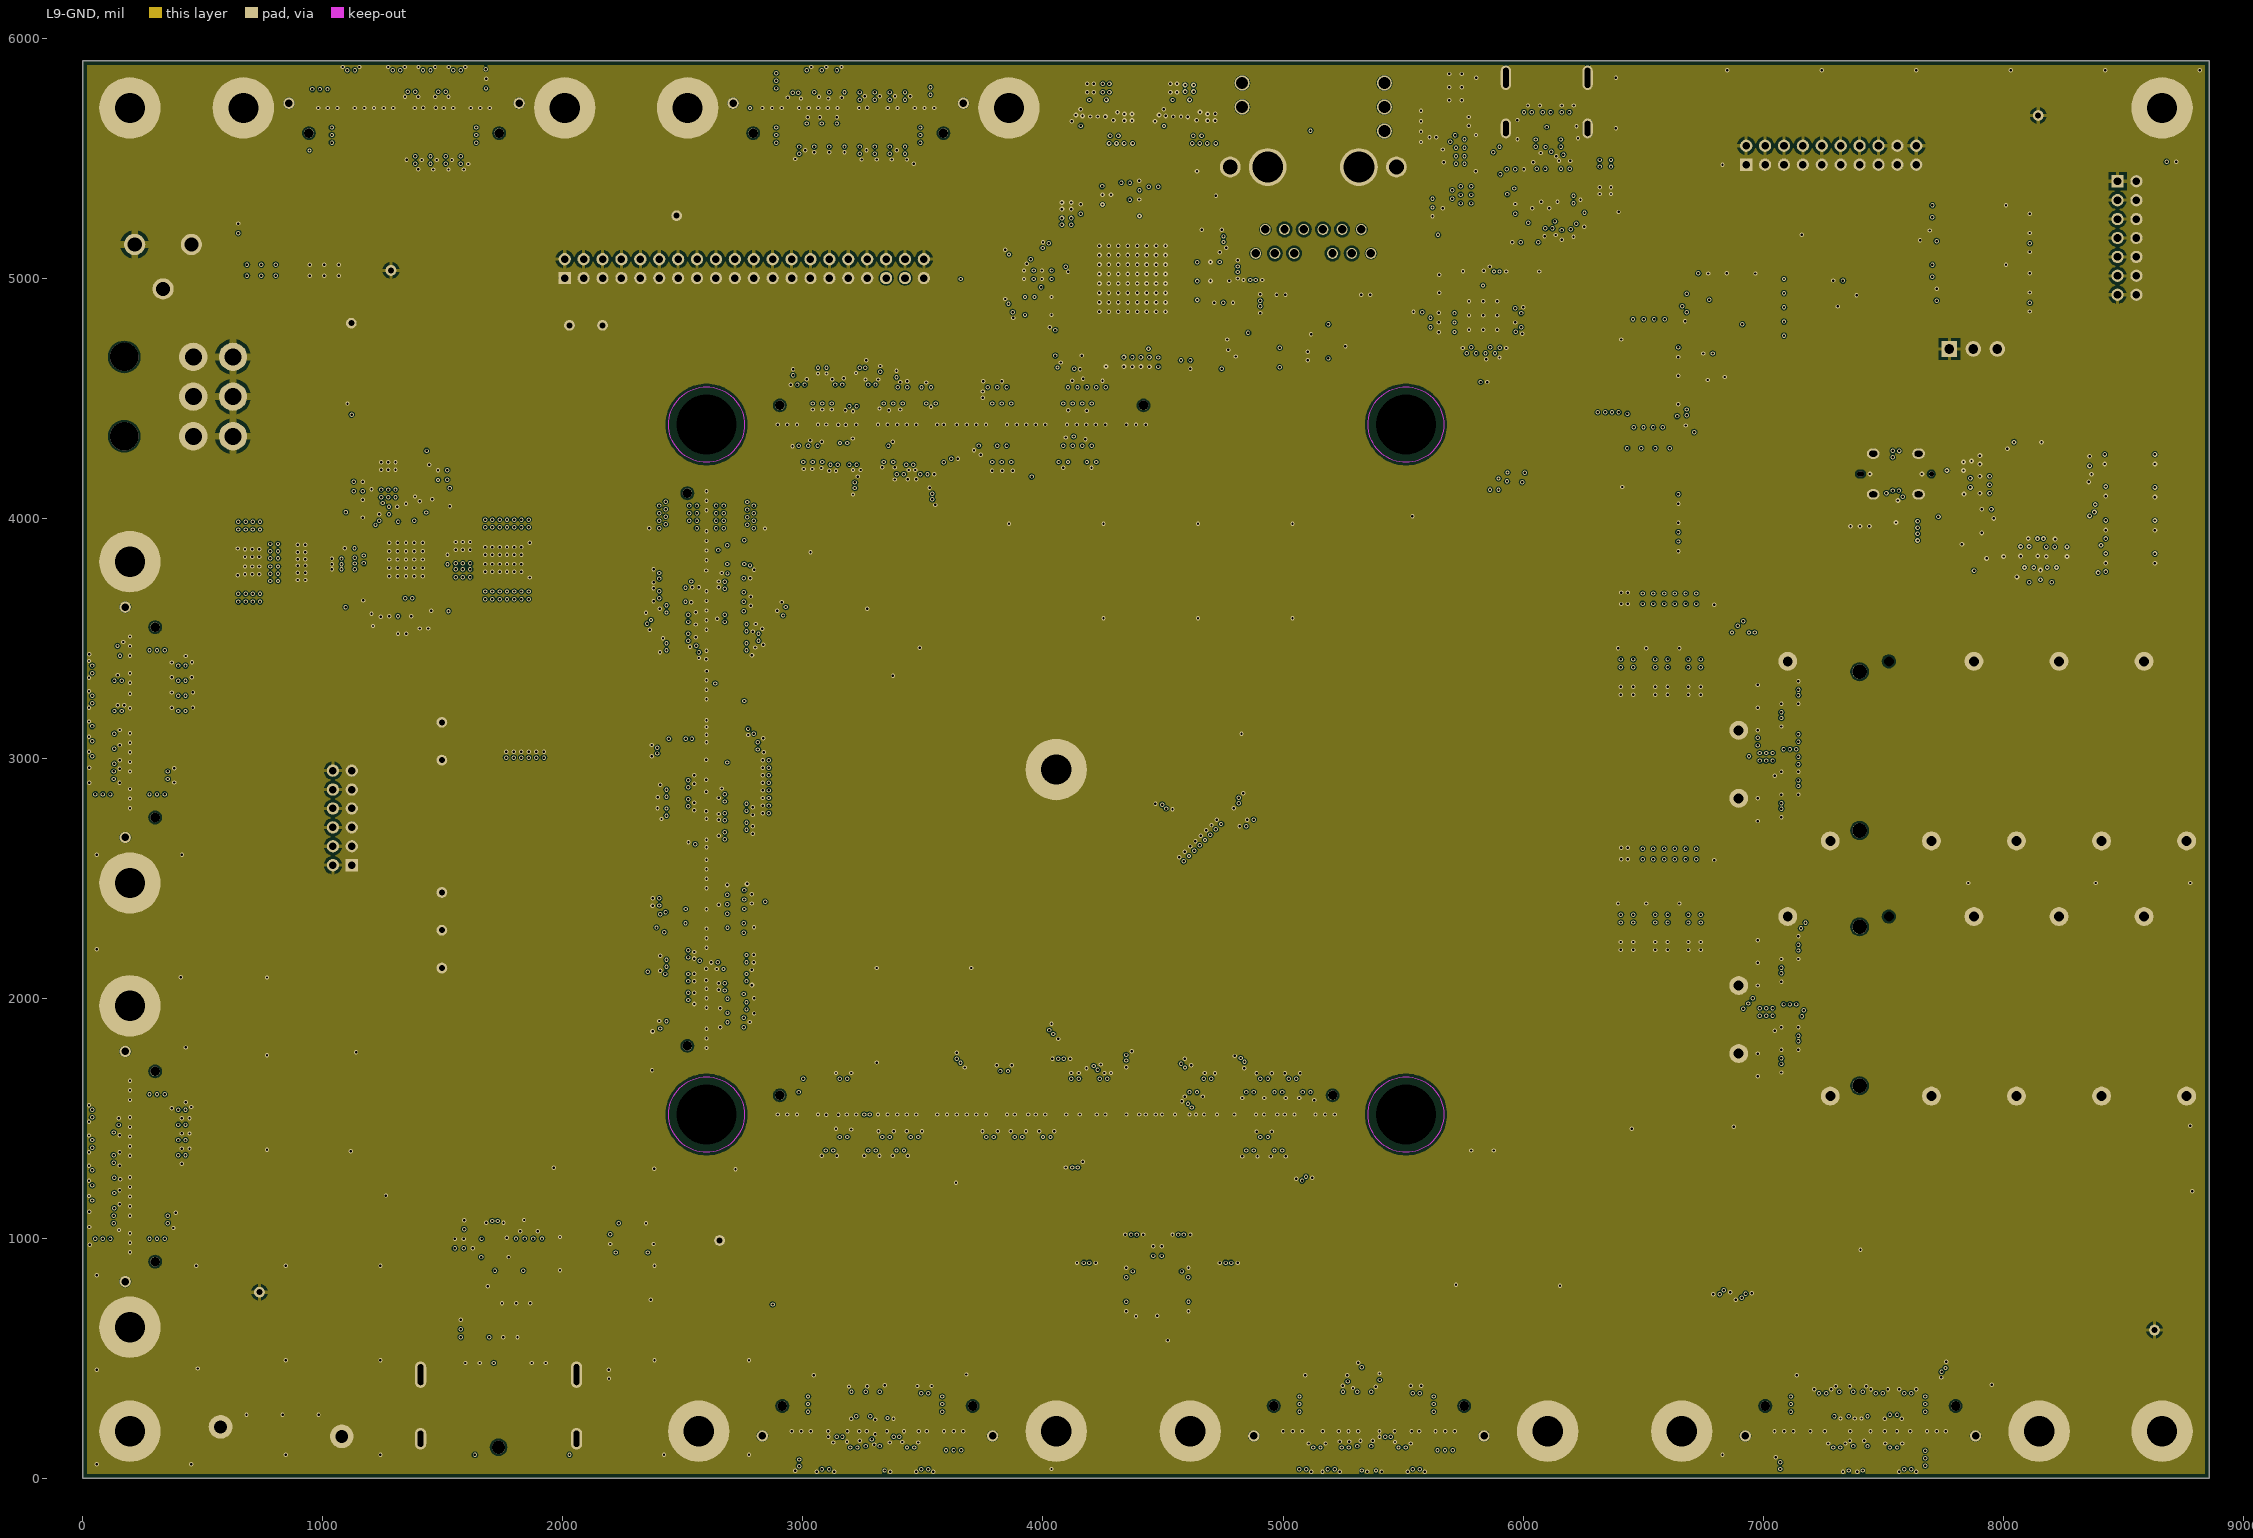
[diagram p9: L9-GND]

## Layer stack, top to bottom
Top Solder: solder mask 0.4, Solder Resist, Dk 3.5
L1-TOP: signal copper 1.4
Dielectric 1-2: prepreg 2.8, PP-006, Dk 4.1
L2-GND: signal copper 1.378
Dielectric 2-3: prepreg 2.8, PP-006, Dk 4.1
L3-PWR: signal copper 1.378
Dielectric 3-4: prepreg 2.8, PP-006, Dk 4.1
L4-GND: signal copper 1.378
Dielectric 4-5: prepreg 2.8, PP-006, Dk 4.1
L5-PWR: signal copper 1.378
Dielectric 5-6: dielectric 12.6, FR-4, Dk 4.8
L6-PWR: signal copper 1.378
Dielectric 6-7: prepreg 2.8, PP-006, Dk 4.1
L7-GND: signal copper 1.378
Dielectric 7-8: prepreg 2.8, PP-006, Dk 4.1
L8-SIG: signal copper 1.378
Dielectric 8-9: prepreg 2.8, PP-006, Dk 4.1
L9-GND: signal copper 1.378
Dielectric 9-10: prepreg 2.8, PP-006, Dk 4.1
L10-BOT: signal copper 1.4
Bottom Solder: solder mask 0.4, Solder Resist, Dk 3.5

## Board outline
0,0 8858.27,0 8858.27,5905.51 0,5905.51

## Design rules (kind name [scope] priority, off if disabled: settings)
BoardOutlineClearance [All] p1: gap=17 ignorepadtopadclearanceinfootprint=FALSE
Clearance Clearance_DiffPairs_GNDPlane [(InDifferentialPairClass('All Differential Pairs')) and not TouchesRoom('USB3_Switch') vs InNet('DGND') and (OnLayer('L2-GND') OR OnLayer('L4-GND') OR OnLayer('L7-GND') OR OnLayer('L9-GND'))] p1: gap=15 ignorepadtopadclearanceinfootprint=TRUE except(0: Arc-Hole Track-Hole SMDPad-Hole THPad-Hole Via-Hole Fill-Hole Poly-Hole Region-Hole Text-Hole; 4.95: Arc-Arc Arc-Track Track-Track; 5: Arc-SMDPad Arc-THPad Arc-Via Arc-Text Track-SMDPad Track-THPad Track-Via Track-Text SMDPad-Via SMDPad-Text THPad-Via THPad-Text Via-Via Via-Text Text-Text; 5.5: SMDPad-SMDPad; 6: SMDPad-THPad; 7: THPad-THPad Fill-Text Poly-Text Region-Text; 8: Via-Fill Via-Poly Via-Region)
Clearance Clearance_DiffPairs [(InDifferentialPairClass('All Differential Pairs')) and not TouchesRoom('USB3_Switch')] p2: gap=15 ignorepadtopadclearanceinfootprint=TRUE except(0: Arc-Hole Track-Hole SMDPad-Hole THPad-Hole Via-Hole Fill-Hole Poly-Hole Region-Hole Text-Hole; 4.95: Arc-Arc Arc-Track Track-Track; 5: Arc-SMDPad Arc-THPad Arc-Via Arc-Text Track-SMDPad Track-THPad Track-Via Track-Text SMDPad-Via SMDPad-Text THPad-Via THPad-Text Via-Via Via-Text Text-Text; 5.5: SMDPad-SMDPad; 6: SMDPad-THPad; 7: THPad-THPad Fill-Text Poly-Text Region-Text)
Clearance [All] p3: gap=5 ignorepadtopadclearanceinfootprint=FALSE except(0: Arc-Hole Track-Hole SMDPad-Hole THPad-Hole Via-Hole Fill-Hole Poly-Hole Region-Hole Text-Hole; 3.5: Track-Track; 4: Track-SMDPad Track-THPad Track-Via; 5.5: SMDPad-SMDPad; 6: SMDPad-THPad; 7: THPad-THPad Fill-Fill Fill-Region Fill-Text Region-Region; 8: Arc-Poly Track-Poly SMDPad-Poly THPad-Poly Via-Poly Fill-Poly; 12: Poly-Poly Poly-Region)
DiffPairsRouting DiffPairsRouting_100ohm [InDifferentialPairClass('DiffPair_100ohm')] p1: maxlimit=5.85 minlimit=1 mostfreqgap=1 toplayer_mingap=5.7 toplayer_maxgap=5.7 toplayer_prefgap=5.7 toplayer_minwidth=3.3 toplayer_maxwidth=3.3 toplayer_prefwidth=3.3 midlayer1_mingap=5.85 midlayer1_prefgap=5.85 midlayer1_minwidth=3.15 midlayer1_maxwidth=3.15 midlayer1_prefwidth=3.15 midlayer2_maxgap=1 midlayer2_minwidth=1 midlayer2_maxwidth=1 midlayer2_prefwidth=1 midlayer3_maxgap=1 midlayer3_minwidth=1 midlayer3_maxwidth=1 midlayer3_prefwidth=1 midlayer4_maxgap=1 midlayer4_minwidth=1 midlayer4_maxwidth=1 midlayer4_prefwidth=1 midlayer5_maxgap=1 midlayer5_minwidth=1 midlayer5_maxwidth=1 midlayer5_prefwidth=1 midlayer6_maxgap=1 midlayer6_minwidth=1 midlayer6_maxwidth=1 midlayer6_prefwidth=1 midlayer7_maxgap=1 midlayer7_minwidth=1 midlayer7_maxwidth=1 midlayer7_prefwidth=1 midlayer12_maxgap=1 midlayer12_minwidth=1 midlayer12_maxwidth=1 midlayer12_prefwidth=1 bottomlayer_mingap=5.7 bottomlayer_maxgap=5.7 bottomlayer_prefgap=5.7 bottomlayer_minwidth=3.3 bottomlayer_maxwidth=3.3 bottomlayer_prefwidth=3.3 maxuncoupledlength=500
DiffPairsRouting DiffPairsRouting_90ohm [InDifferentialPairClass('DiffPair_90ohm')] p2: maxlimit=4.95 minlimit=1 mostfreqgap=1 toplayer_mingap=4.95 toplayer_prefgap=4.95 toplayer_minwidth=4.05 toplayer_maxwidth=4.05 toplayer_prefwidth=4.05 midlayer1_maxgap=1 midlayer1_minwidth=1 midlayer1_maxwidth=1 midlayer1_prefwidth=1 midlayer2_maxgap=1 midlayer2_minwidth=1 midlayer2_maxwidth=1 midlayer2_prefwidth=1 midlayer3_maxgap=1 midlayer3_minwidth=1 midlayer3_maxwidth=1 midlayer3_prefwidth=1 midlayer4_maxgap=1 midlayer4_minwidth=1 midlayer4_maxwidth=1 midlayer4_prefwidth=1 midlayer5_maxgap=1 midlayer5_minwidth=1 midlayer5_maxwidth=1 midlayer5_prefwidth=1 midlayer6_maxgap=1 midlayer6_minwidth=1 midlayer6_maxwidth=1 midlayer6_prefwidth=1 midlayer7_maxgap=1 midlayer7_minwidth=1 midlayer7_maxwidth=1 midlayer7_prefwidth=1 midlayer12_maxgap=1 midlayer12_minwidth=1 midlayer12_maxwidth=1 midlayer12_prefwidth=1 bottomlayer_mingap=4.95 bottomlayer_prefgap=4.95 bottomlayer_minwidth=4.05 bottomlayer_maxwidth=4.05 bottomlayer_prefwidth=4.05 maxuncoupledlength=500
DiffPairsRouting [All] p3: maxlimit=10 minlimit=10 mostfreqgap=10 toplayer_minwidth=15 toplayer_maxwidth=15 toplayer_prefwidth=15 midlayer1_minwidth=15 midlayer1_maxwidth=15 midlayer1_prefwidth=15 midlayer2_minwidth=15 midlayer2_maxwidth=15 midlayer2_prefwidth=15 midlayer3_minwidth=15 midlayer3_maxwidth=15 midlayer3_prefwidth=15 midlayer4_minwidth=15 midlayer4_maxwidth=15 midlayer4_prefwidth=15 midlayer5_minwidth=15 midlayer5_maxwidth=15 midlayer5_prefwidth=15 midlayer6_minwidth=15 midlayer6_maxwidth=15 midlayer6_prefwidth=15 midlayer7_minwidth=15 midlayer7_maxwidth=15 midlayer7_prefwidth=15 midlayer12_minwidth=15 midlayer12_maxwidth=15 midlayer12_prefwidth=15 bottomlayer_minwidth=15 bottomlayer_maxwidth=15 bottomlayer_prefwidth=15 maxuncoupledlength=500
HoleSize [All] p1: absolutevalues=TRUE maxlimit=250 minlimit=10 maxpercent=80.000 minpercent=20.000
HoleToHoleClearance [All] p1: gap=12 allowstackedmicrovias=TRUE
MatchedLengths MatchedLengths_JTAG [InxSignalClass('xSignals_JTAG')] p1: tolerance=10 checknetsindiffpair=FALSE checkdiffpairvsdiffpair=TRUE checkxsignals=TRUE checkothers=TRUE
MatchedLengths MatchedLengths_PORTA [InxSignalClass('xSignals_SZG_PORTA')] p2: tolerance=10 checknetsindiffpair=FALSE checkdiffpairvsdiffpair=TRUE checkxsignals=TRUE checkothers=TRUE
MatchedLengths MatchedLengths_PORTB [InxSignalClass('xSignals_SZG_PORTB')] p3: tolerance=10 checknetsindiffpair=FALSE checkdiffpairvsdiffpair=TRUE checkxsignals=TRUE checkothers=TRUE
MatchedLengths MatchedLengths_PORTC [InxSignalClass('xSignals_SZG_PORTC')] p4: tolerance=10 checknetsindiffpair=FALSE checkdiffpairvsdiffpair=TRUE checkxsignals=TRUE checkothers=TRUE
MatchedLengths MatchedLengths_PORTD [InxSignalClass('xSignals_SZG_PORTD')] p5: tolerance=10 checknetsindiffpair=FALSE checkdiffpairvsdiffpair=TRUE checkxsignals=TRUE checkothers=TRUE
MatchedLengths MatchedLengths_PORTE [InxSignalClass('xSignals_SZG_PORTE')] p6: tolerance=10 checknetsindiffpair=FALSE checkdiffpairvsdiffpair=TRUE checkxsignals=TRUE checkothers=TRUE
MatchedLengths MatchedLengths_PORTF [InxSignalClass('xSignals_SZG_PORTF')] p7: tolerance=10 checknetsindiffpair=FALSE checkdiffpairvsdiffpair=TRUE checkxsignals=TRUE checkothers=TRUE
MatchedLengths MatchedLengths_PORTG [InxSignalClass('xSignals_SZG_PORTG')] p8: tolerance=10 checknetsindiffpair=FALSE checkdiffpairvsdiffpair=TRUE checkxsignals=TRUE checkothers=TRUE
MatchedLengths MatchedLengths_ETH_RGMII [InxSignalClass('xSignals_ETH_PHY_RGMII')] p9: tolerance=200 checknetsindiffpair=FALSE checkdiffpairvsdiffpair=TRUE checkxsignals=TRUE checkothers=TRUE
MatchedLengths MatchedLengths_ETH_TXRX [InxSignalClass('xSignals_ETH_PHY_TXRX')] p10: tolerance=100 checknetsindiffpair=FALSE checkdiffpairvsdiffpair=TRUE checkxsignals=TRUE checkothers=TRUE
MatchedLengths MatchedLengths_DiffPair [InxSignalClass('All xSignals')] p11: tolerance=5 checknetsindiffpair=TRUE checkdiffpairvsdiffpair=FALSE checkxsignals=FALSE checkothers=FALSE
MinimumSolderMaskSliver [All] p1: minsoldermaskwidth=2.5
PlaneClearance [All] p1: clearance=8
PlaneConnect ViaNoConnect [Name Like 'ViaNoConnect*'] p1: planeconnectstyle=NoConnect reliefexpansion=20 reliefentries=4 reliefconductorwidth=10 reliefairgap=10
PlaneConnect [All] p2: planeconnectstyle=Relief reliefexpansion=20 reliefentries=4 reliefconductorwidth=10 reliefairgap=10
PolygonConnect MC-Thermal-Relief [InComponent('MC1') or InComponent('MC2') or InComponent('MC3')] p1: connectstyle=Relief reliefconductorwidth=10 reliefentries=4 polygonreliefangle="90 Angle" airgapwidth=10
PolygonConnect ViaNoConnectPoly [Name Like 'Free-ViaNoConnect*'] p2: connectstyle=NoConnect reliefconductorwidth=10 reliefentries=4 polygonreliefangle="90 Angle" airgapwidth=10
PolygonConnect Power_Thermal_TH [IsThruPin and InNet('DGND') and (HasFootprint('0455580003') or HasFootprint('CUI-PJ102A'))] p3: connectstyle=Relief reliefconductorwidth=30 reliefentries=4 polygonreliefangle="90 Angle" airgapwidth=15
PolygonConnect Thermal_TH_DGND [IsThruPin and InNet('DGND')] p4: connectstyle=Relief reliefconductorwidth=15 reliefentries=4 polygonreliefangle="90 Angle" airgapwidth=12
PolygonConnect [All] p5: connectstyle=Direct reliefconductorwidth=10 reliefentries=4 polygonreliefangle="90 Angle" airgapwidth=10
RoomDefinition breakout [False] p1: selectionmemoryflags=1 confinementstyle=ConfineIn formatcopy=TRUE lockcomponents=FALSE outline 4051.18,4708.66 4051.18,5279.53 4653.54,5279.53 4653.54,4708.66
RoomDefinition USB3_Switch [False] p2: confinementstyle=ConfineIn formatcopy=TRUE lockcomponents=FALSE outline 5995,5370 6203,5370 6203,5231 5995,5231
RoutingVias [All] p1: holewidth=10 width=18 viastyle="Through Hole" minholewidth=10 minwidth=18 maxholewidth=28 maxwidth=50
SilkToSilkClearance [All] p1: silktosilkclearance=0.1
SilkToSolderMaskClearance [IsPad] p1: minsilkscreentomaskgap=2 clearancetoexposedcopper=FALSE
SolderMaskExpansion [All] p1: expansion=2 istentingtop=FALSE
SupplyNets "Schematic Supply Nets_20" [InNet('FT232_VCCD')] p1: voltage=0.000
SupplyNets "Schematic Supply Nets_19" [InNet('VREF_67')] p2: voltage=0.000
SupplyNets "Schematic Supply Nets_18" [InNet('+5V_SZG')] p3: voltage=0.000
SupplyNets "Schematic Supply Nets_17" [InNet('VDDD')] p4: voltage=0.000
SupplyNets "Schematic Supply Nets_16" [InNet('VCCO_28')] p5: voltage=0.000
SupplyNets "Schematic Supply Nets_15" [InNet('+5V_AUX')] p6: voltage=0.000
SupplyNets "Schematic Supply Nets_14" [InNet('VREF_28')] p7: voltage=0.000
SupplyNets "Schematic Supply Nets_13" [InNet('USB_VBUS')] p8: voltage=0.000
SupplyNets "Schematic Supply Nets_12" [InNet('VREF_68')] p9: voltage=0.000
SupplyNets "Schematic Supply Nets_11" [InNet('FT232_VREGIN')] p10: voltage=0.000
SupplyNets "Schematic Supply Nets_10" [InNet('DGND')] p11: voltage=0.000
SupplyNets "Schematic Supply Nets_9" [InNet('VCCO_87_88')] p12: voltage=0.000
SupplyNets "Schematic Supply Nets_8" [InNet('VCCO_67')] p13: voltage=0.000
SupplyNets "Schematic Supply Nets_7" [InNet('+1.1V_ETH')] p14: voltage=0.000
SupplyNets "Schematic Supply Nets_6" [InNet('+VDCIN')] p15: voltage=0.000
SupplyNets "Schematic Supply Nets_5" [InNet('VCCO_68')] p16: voltage=0.000
SupplyNets "Schematic Supply Nets_4" [InNet('+2.5V_ETH')] p17: voltage=0.000
SupplyNets "Schematic Supply Nets_3" [InNet('+3.3V_AUX')] p18: voltage=0.000
SupplyNets "Schematic Supply Nets_2" [InNet('+1.8V')] p19: voltage=0.000
SupplyNets "Schematic Supply Nets_1" [InNet('+3.3V_QSFP')] p20: voltage=0.000
SupplyNets "Schematic Supply Nets" [InNet('+3.3V')] p21: voltage=0.000
Width Width-50ohm [InNetClass('50ohm')] p1: maxlimit=4.55 minlimit=1 preferedwidth=1 toplayer_minwidth=4.55 toplayer_prefwidth=4.55 midlayer1_minwidth=4.05 midlayer1_maxwidth=4.05 midlayer1_prefwidth=4.05 midlayer2_maxwidth=1 midlayer3_maxwidth=1 midlayer4_maxwidth=1 midlayer5_maxwidth=1 midlayer6_maxwidth=1 midlayer7_maxwidth=1 midlayer12_maxwidth=1 bottomlayer_minwidth=4.55 bottomlayer_prefwidth=4.55 minimp=50.000000 maximp=50.000000 favimp=50.000000
Width Width-Power [InNetClass('Power')] p2: maxlimit=100 minlimit=5 preferedwidth=10 midlayer1_minwidth=10 midlayer2_minwidth=10 midlayer3_minwidth=10 midlayer4_minwidth=10 midlayer5_minwidth=10 midlayer6_minwidth=10 midlayer7_minwidth=10 midlayer12_minwidth=10 minimp=50.000000 maximp=50.000000 favimp=50.000000
Width [All] p3: maxlimit=100 minlimit=4 preferedwidth=10 minimp=50.000000 maximp=50.000000 favimp=50.000000
22 further rules are at their usual default settings.

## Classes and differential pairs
component class JTAG: C1 C9 C10 C11 C12 C13 C14 C15 C16 C17 C18 C19 C22 C23 C28 C29 C30 C31 C32 C33 C34 C35 C36 C37 C38 C39 C40 C41 C42 D5 FB2 FB3 FB4 FB5 J2 J21 R13 R19 R20 R21 R22 R23 R24 R25 R26 R27 R28 U3 U4 U5 U6 U7 U20 Y4
net class SZG_PORTG: SZG_PORTG_C2P_CLKN SZG_PORTG_C2P_CLKP SZG_PORTG_P2C_CLKN SZG_PORTG_P2C_CLKP SZG_PORTG_REFCLKN SZG_PORTG_REFCLKP SZG_PORTG_RX0N SZG_PORTG_RX0P SZG_PORTG_RX1N SZG_PORTG_RX1P SZG_PORTG_RX2N SZG_PORTG_RX2P SZG_PORTG_RX3N SZG_PORTG_RX3P SZG_PORTG_S0 SZG_PORTG_S1 SZG_PORTG_S2 SZG_PORTG_S3 SZG_PORTG_S4 SZG_PORTG_S5 SZG_PORTG_S6 SZG_PORTG_S7 SZG_PORTG_S8 SZG_PORTG_S9 SZG_PORTG_TX0N SZG_PORTG_TX0P SZG_PORTG_TX1N SZG_PORTG_TX1P SZG_PORTG_TX2N SZG_PORTG_TX2P SZG_PORTG_TX3N SZG_PORTG_TX3P
component class DisplayPort-Source: C170 C171 C182 C183 C185 C187 C189 C190 J20 R153 R154 R155 R156 R157 R158 R159 R167 R168 R169 R181 U24
component class Clocks: C3 C4 C5 C6 C7 C8 TP24 TP25 TP26 TP27 TP28 TP29 TP30 TP31 U2 Y2
component class USB: C69 C70 C71 C72 C73 C74 C75 C76 C77 C78 C79 C80 C81 C174 C175 C220 C221 D1 FB1 J16 R12 R65 R66 R67 R68 R69 R70 R71 R72 R73 R74 R75 R76 R77 R78 R79 R80 R81 R82 R83 U12 U13 U14 Y3
component class Ethernet: C90 C91 C92 C93 C94 C95 C96 C97 C98 C99 C100 C101 C102 C103 C104 C105 C106 C107 C108 C109 C110 C111 C112 C159 C163 C164 C168 C214 C215 D2 D3 J17 Q2 Q3 R62 R63 R64 R84 R85 R86 R87 R88 R89 R90 R91 R92 R93 R94 R95 R96 R97 R98 R99 R100 R101 R102 R103 R104 R105 R106 R107 R108 R109 R110 R111 R112 R113 R114 R115 R116 R117 R118 R119 R140 R183 R184 U15 U18 Y1
net class QSFP_CTRL: QSFP1_INT_B QSFP1_LP_MODE QSFP1_MODPRS_B QSFP1_MODSEL_B QSFP1_RESET_B QSFP1_SCL QSFP1_SDA QSFP2_INT_B QSFP2_LP_MODE QSFP2_MODPRS_B QSFP2_MODSEL_B QSFP2_RESET_B QSFP2_SCL QSFP2_SDA QSFP_1_INT_B_3V3 QSFP_1_LP_MODE_3V3 QSFP_1_MODPRS_B_3V3 QSFP_1_MODSEL_B_3V3 QSFP_1_RESET_B_3V3 QSFP_1_SCL_3V3 QSFP_1_SDA_3V3 QSFP_2_INT_B_3V3 QSFP_2_LP_MODE_3V3 QSFP_2_MODPRS_B_3V3 QSFP_2_MODSEL_B_3V3 QSFP_2_RESET_B_3V3 QSFP_2_SCL_3V3 QSFP_2_SDA_3V3
net class SZG_PORTF: SZG_PORTF_C2P_CLKN SZG_PORTF_C2P_CLKP SZG_PORTF_P2C_CLKN SZG_PORTF_P2C_CLKP SZG_PORTF_REFCLKN SZG_PORTF_REFCLKP SZG_PORTF_RX0N SZG_PORTF_RX0P SZG_PORTF_RX1N SZG_PORTF_RX1P SZG_PORTF_RX2N SZG_PORTF_RX2P SZG_PORTF_RX3N SZG_PORTF_RX3P SZG_PORTF_S0 SZG_PORTF_S1 SZG_PORTF_S2 SZG_PORTF_S3 SZG_PORTF_S4 SZG_PORTF_S5 SZG_PORTF_S6 SZG_PORTF_S7 SZG_PORTF_S8 SZG_PORTF_S9 SZG_PORTF_TX0N SZG_PORTF_TX0P SZG_PORTF_TX1N SZG_PORTF_TX1P SZG_PORTF_TX2N SZG_PORTF_TX2P SZG_PORTF_TX3N SZG_PORTF_TX3P
net class SZG_PORTE: SZG_PORTE_C2P_CLKN SZG_PORTE_C2P_CLKP SZG_PORTE_P2C_CLKN SZG_PORTE_P2C_CLKP SZG_PORTE_REFCLKN SZG_PORTE_REFCLKP SZG_PORTE_RX0N SZG_PORTE_RX0P SZG_PORTE_RX1N SZG_PORTE_RX1P SZG_PORTE_RX2N SZG_PORTE_RX2P SZG_PORTE_RX3N SZG_PORTE_RX3P SZG_PORTE_S0 SZG_PORTE_S1 SZG_PORTE_S2 SZG_PORTE_S3 SZG_PORTE_S4 SZG_PORTE_S5 SZG_PORTE_S6 SZG_PORTE_S7 SZG_PORTE_S8 SZG_PORTE_S9 SZG_PORTE_TX0N SZG_PORTE_TX0P SZG_PORTE_TX1N SZG_PORTE_TX1P SZG_PORTE_TX2N SZG_PORTE_TX2P SZG_PORTE_TX3N SZG_PORTE_TX3P
net class SZG_PORTD: SZG_PORTD_C2P_CLKN SZG_PORTD_C2P_CLKP SZG_PORTD_P2C_CLKN SZG_PORTD_P2C_CLKP SZG_PORTD_S0_D0P SZG_PORTD_S1_D1P SZG_PORTD_S2_D0N SZG_PORTD_S3_D1N SZG_PORTD_S4_D2P SZG_PORTD_S5_D3P SZG_PORTD_S6_D2N SZG_PORTD_S7_D3N SZG_PORTD_S8_D4P SZG_PORTD_S9_D5P SZG_PORTD_S10_D4N SZG_PORTD_S11_D5N SZG_PORTD_S12_D6P SZG_PORTD_S13_D7P SZG_PORTD_S14_D6N SZG_PORTD_S15_D7N SZG_PORTD_S16 SZG_PORTD_S17 SZG_PORTD_S18 SZG_PORTD_S19 SZG_PORTD_S20 SZG_PORTD_S21 SZG_PORTD_S22 SZG_PORTD_S23 SZG_PORTD_S24 SZG_PORTD_S25 SZG_PORTD_S26 SZG_PORTD_S27
net class SZG_PORTC: SZG_PORTC_C2P_CLKN SZG_PORTC_C2P_CLKP SZG_PORTC_P2C_CLKN SZG_PORTC_P2C_CLKP SZG_PORTC_S0_D0P SZG_PORTC_S1_D1P SZG_PORTC_S2_D0N SZG_PORTC_S3_D1N SZG_PORTC_S4_D2P SZG_PORTC_S5_D3P SZG_PORTC_S6_D2N SZG_PORTC_S7_D3N SZG_PORTC_S8_D4P SZG_PORTC_S9_D5P SZG_PORTC_S10_D4N SZG_PORTC_S11_D5N SZG_PORTC_S12_D6P SZG_PORTC_S13_D7P SZG_PORTC_S14_D6N SZG_PORTC_S15_D7N SZG_PORTC_S16 SZG_PORTC_S17 SZG_PORTC_S18 SZG_PORTC_S19 SZG_PORTC_S20 SZG_PORTC_S21 SZG_PORTC_S22 SZG_PORTC_S23 SZG_PORTC_S24 SZG_PORTC_S25 SZG_PORTC_S26 SZG_PORTC_S27
net class SZG_PORTB: SZG_PORTB_C2P_CLKN SZG_PORTB_C2P_CLKP SZG_PORTB_P2C_CLKN SZG_PORTB_P2C_CLKP SZG_PORTB_S0_D0P SZG_PORTB_S1_D1P SZG_PORTB_S2_D0N SZG_PORTB_S3_D1N SZG_PORTB_S4_D2P SZG_PORTB_S5_D3P SZG_PORTB_S6_D2N SZG_PORTB_S7_D3N SZG_PORTB_S8_D4P SZG_PORTB_S9_D5P SZG_PORTB_S10_D4N SZG_PORTB_S11_D5N SZG_PORTB_S12_D6P SZG_PORTB_S13_D7P SZG_PORTB_S14_D6N SZG_PORTB_S15_D7N SZG_PORTB_S16 SZG_PORTB_S17 SZG_PORTB_S18 SZG_PORTB_S19 SZG_PORTB_S20 SZG_PORTB_S21 SZG_PORTB_S22 SZG_PORTB_S23 SZG_PORTB_S24 SZG_PORTB_S25 SZG_PORTB_S26 SZG_PORTB_S27
net class SZG_PORTA: SZG_PORTA_C2P_1 SZG_PORTA_C2P_2 SZG_PORTA_P2C_1 SZG_PORTA_P2C_2 SZG_PORTA_S0 SZG_PORTA_S1 SZG_PORTA_S2 SZG_PORTA_S3 SZG_PORTA_S4 SZG_PORTA_S5 SZG_PORTA_S6 SZG_PORTA_S7 SZG_PORTA_S8 SZG_PORTA_S9 SZG_PORTA_S10 SZG_PORTA_S11 SZG_PORTA_S12 SZG_PORTA_S13 SZG_PORTA_S14 SZG_PORTA_S15 SZG_PORTA_S16 SZG_PORTA_S17 SZG_PORTA_S18 SZG_PORTA_S19 SZG_PORTA_S20 SZG_PORTA_S21 SZG_PORTA_S22 SZG_PORTA_S23 SZG_PORTA_S24 SZG_PORTA_S25 SZG_PORTA_S26 SZG_PORTA_S27
differential pair class DiffPair_90ohm: DP_USB_D DP_USB_SSRX DP_USB_SSRX1 DP_USB_SSRX2 DP_USB_SSTX DP_USB_SSTX1 DP_USB_SSTX1_C DP_USB_SSTX2 DP_USB_SSTX2_C DP_USB_SSTX_C
net class PS_Config: PS_DONE PS_ERROR_OUT PS_ERROR_STATUS PS_INIT_B PS_MODE0 PS_MODE1 PS_MODE2 PS_MODE3 PS_PROG_B PS_SRST_B
net class 50ohm: GIGE_MDC GIGE_MDIO GIGE_RX_CLK GIGE_RX_DV GIGE_RXD0 GIGE_RXD1 GIGE_RXD2 GIGE_RXD3 GIGE_TX_CLK GIGE_TX_EN GIGE_TXD0 GIGE_TXD1 GIGE_TXD2 GIGE_TXD3 PS_B500_MIO0 PS_B500_MIO1 PS_B500_MIO2 PS_B500_MIO4 PS_B500_MIO5 PS_B500_MIO7 PS_B500_MIO8 PS_B500_MIO11 PS_B500_MIO12 PS_B500_MIO13 PS_B500_MIO19 PS_B500_MIO20 PS_B500_MIO21 PS_B500_MIO22 PS_B500_MIO23 PS_B500_MIO24 PS_B500_MIO25 SZG_PORTA_C2P_1 SZG_PORTA_C2P_2 SZG_PORTA_P2C_1 SZG_PORTA_P2C_2 SZG_PORTA_S0 SZG_PORTA_S1 SZG_PORTA_S2 SZG_PORTA_S3 SZG_PORTA_S4 SZG_PORTA_S5 SZG_PORTA_S6 SZG_PORTA_S7 SZG_PORTA_S8 SZG_PORTA_S9 SZG_PORTA_S10 SZG_PORTA_S11 SZG_PORTA_S12 SZG_PORTA_S13 SZG_PORTA_S14 SZG_PORTA_S15 SZG_PORTA_S16 SZG_PORTA_S17 SZG_PORTA_S18 SZG_PORTA_S19 SZG_PORTA_S20 SZG_PORTA_S21 SZG_PORTA_S22 SZG_PORTA_S23 SZG_PORTA_S24 SZG_PORTA_S25 SZG_PORTA_S26 SZG_PORTA_S27 SZG_PORTB_S16 SZG_PORTB_S17 SZG_PORTB_S18 SZG_PORTB_S19 SZG_PORTB_S20 SZG_PORTB_S21 SZG_PORTB_S22 SZG_PORTB_S23 SZG_PORTB_S24 SZG_PORTB_S25 SZG_PORTB_S26 SZG_PORTB_S27 SZG_PORTC_S16 SZG_PORTC_S17 SZG_PORTC_S18 SZG_PORTC_S19 SZG_PORTC_S20 SZG_PORTC_S21 SZG_PORTC_S22 SZG_PORTC_S23 SZG_PORTC_S24 SZG_PORTC_S25 SZG_PORTC_S26 SZG_PORTC_S27 SZG_PORTD_S16 SZG_PORTD_S17 SZG_PORTD_S18 SZG_PORTD_S19 SZG_PORTD_S20 SZG_PORTD_S21 SZG_PORTD_S22 SZG_PORTD_S23 SZG_PORTD_S24 SZG_PORTD_S25 SZG_PORTD_S26 SZG_PORTD_S27 SZG_PORTE_S0 SZG_PORTE_S1 SZG_PORTE_S2 SZG_PORTE_S3 SZG_PORTE_S4 SZG_PORTE_S5 SZG_PORTE_S6 SZG_PORTE_S7 SZG_PORTE_S8 SZG_PORTE_S9 SZG_PORTF_S0 SZG_PORTF_S1 SZG_PORTF_S2 SZG_PORTF_S3 SZG_PORTF_S4 SZG_PORTF_S5 SZG_PORTF_S6 SZG_PORTF_S7 SZG_PORTF_S8 SZG_PORTF_S9 USB_CLKOUT USB_DATA0 USB_DATA1 USB_DATA2 USB_DATA3 USB_DATA4 USB_DATA5 USB_DATA6 USB_DATA7 USB_DIR USB_NXT USB_RESET_B USB_STP
differential pair class DiffPair_100ohm: DP_B68_L3 DP_B68_L13 DP_B68_L14 DP_B68_L15 DP_B68_L16 DP_CLK0 DP_CLK1 DP_CLK2 DP_CLK3 DP_DISPLAYPORT_PL_SNK_AUX DP_DISPLAYPORT_PL_SNK_AUX_C DP_DISPLAYPORT_PL_SNK_CONN_AUX DP_DISPLAYPORT_PL_SNK_CONN_AUX_C DP_DISPLAYPORT_PL_SNK_CONN_LANE0 DP_DISPLAYPORT_PL_SNK_CONN_LANE1 DP_DISPLAYPORT_PL_SNK_LANE0 DP_DISPLAYPORT_PL_SNK_LANE0_C DP_DISPLAYPORT_PL_SNK_LANE1 DP_DISPLAYPORT_PL_SNK_LANE1_C DP_DISPLAYPORT_PL_SRC_AUX DP_DISPLAYPORT_PL_SRC_AUX_C DP_DISPLAYPORT_PL_SRC_CONN_LANE0 DP_DISPLAYPORT_PL_SRC_CONN_LANE0_C DP_DISPLAYPORT_PL_SRC_CONN_LANE1 DP_DISPLAYPORT_PL_SRC_CONN_LANE1_C DP_DISPLAYPORT_PL_SRC_LANE0 DP_DISPLAYPORT_PL_SRC_LANE0_C DP_DISPLAYPORT_PL_SRC_LANE1 DP_DISPLAYPORT_PL_SRC_LANE1_N_C DP_DISPLAYPORT_PS_SRC_AUX DP_DISPLAYPORT_PS_SRC_AUX_C DP_DISPLAYPORT_PS_SRC_CONN_LANE0 DP_DISPLAYPORT_PS_SRC_CONN_LANE0_C DP_DISPLAYPORT_PS_SRC_CONN_LANE1 DP_DISPLAYPORT_PS_SRC_CONN_LANE1_C DP_DISPLAYPORT_PS_SRC_LANE0 DP_DISPLAYPORT_PS_SRC_LANE0_C DP_DISPLAYPORT_PS_SRC_LANE1 DP_DISPLAYPORT_PS_SRC_LANE1_C DP_ETH_TXRX_A DP_ETH_TXRX_A_ DP_ETH_TXRX_B DP_ETH_TXRX_B_ DP_ETH_TXRX_C DP_ETH_TXRX_C_ DP_ETH_TXRX_D DP_ETH_TXRX_D_ DP_FPX1301_RX0 DP_FPX1301_RX0_C DP_FPX1301_RX1 DP_FPX1301_RX1_C DP_FPX1301_TX0 DP_FPX1301_TX0_C DP_FPX1301_TX1 DP_FPX1301_TX1_C DP_PORTA_C2P_CLK DP_PORTA_D0 DP_PORTA_D1 DP_PORTA_D2 DP_PORTA_D3 DP_PORTA_D4 DP_PORTA_D5 DP_PORTA_D6 DP_PORTA_D7 DP_PORTA_P2C_CLK DP_PORTB_C2P_CLK DP_PORTB_D0 DP_PORTB_D1 DP_PORTB_D2 DP_PORTB_D3 DP_PORTB_D4 DP_PORTB_D5 DP_PORTB_D6 DP_PORTB_D7 DP_PORTB_P2C_CLK DP_PORTC_C2P_CLK DP_PORTC_D0 DP_PORTC_D1 DP_PORTC_D2 DP_PORTC_D3 DP_PORTC_D4 DP_PORTC_D5 DP_PORTC_D6 DP_PORTC_D7 DP_PORTC_P2C_CLK DP_PORTD_C2P_CLK DP_PORTD_D0 DP_PORTD_D1 DP_PORTD_D2 DP_PORTD_D3 DP_PORTD_D4 DP_PORTD_D5 DP_PORTD_D6 DP_PORTD_D7 DP_PORTD_P2C_CLK DP_PORTE_C2P DP_PORTE_P2C_CLK DP_PORTE_REFCLK DP_PORTE_RX0 DP_PORTE_RX1 DP_PORTE_RX2 DP_PORTE_RX3 DP_PORTE_TX0 DP_PORTE_TX1 DP_PORTE_TX2 DP_PORTE_TX3 DP_PORTF_C2P_CLK DP_PORTF_P2C_CLK DP_PORTF_REFCLK DP_PORTF_RX0 DP_PORTF_RX1 DP_PORTF_RX2 DP_PORTF_RX3 DP_PORTF_TX0 DP_PORTF_TX1 DP_PORTF_TX2 DP_PORTF_TX3 DP_PORTG_C2P_CLK DP_PORTG_P2C_CLK DP_PORTG_REFCLK DP_PORTG_RX0 DP_PORTG_RX1 DP_PORTG_RX2 DP_PORTG_RX3 DP_PORTG_TX0 DP_PORTG_TX1 DP_PORTG_TX2 DP_PORTG_TX3 DP_QSFP1_RX1 DP_QSFP1_RX2 DP_QSFP1_RX3 DP_QSFP1_RX4 DP_QSFP1_TX1 DP_QSFP1_TX2 DP_QSFP1_TX3 DP_QSFP1_TX4 DP_QSFP2_RX1 DP_QSFP2_RX2 DP_QSFP2_RX3 DP_QSFP2_RX4 DP_QSFP2_TX1 DP_QSFP2_TX2 DP_QSFP2_TX3 DP_QSFP2_TX4 DP_SATA_TXA DP_SATA_TXA_C DP_SATA_TXB DP_SATA_TXB_C DP_XADC_V
net class Power: +1.1V_ETH +3.3V +3.3V_AUX +3.3V_QSFP +5V_AUX +5V_SZG +VDCIN DGND NetC53_2 USB_VBUS VCCO_28 VCCO_67 VCCO_68 VDDD VREF_28 VREF_67 VREF_68
differential pair DP_PORTG_P2C_CLK: +SZG_PORTG_P2C_CLKP -SZG_PORTG_P2C_CLKN
differential pair DP_PORTG_TX3: +SZG_PORTG_TX3P -SZG_PORTG_TX3N
differential pair DP_PORTG_TX2: +SZG_PORTG_TX2P -SZG_PORTG_TX2N
differential pair DP_PORTG_TX1: +SZG_PORTG_TX1P -SZG_PORTG_TX1N
differential pair DP_PORTG_TX0: +SZG_PORTG_TX0P -SZG_PORTG_TX0N
differential pair DP_PORTG_RX3: +SZG_PORTG_RX3P -SZG_PORTG_RX3N
differential pair DP_PORTG_RX2: +SZG_PORTG_RX2P -SZG_PORTG_RX2N
differential pair DP_PORTG_RX1: +SZG_PORTG_RX1P -SZG_PORTG_RX1N
differential pair DP_PORTG_RX0: +SZG_PORTG_RX0P -SZG_PORTG_RX0N
differential pair DP_PORTG_REFCLK: +SZG_PORTG_REFCLKP -SZG_PORTG_REFCLKN
differential pair DP_PORTG_C2P_CLK: +SZG_PORTG_C2P_CLKP -SZG_PORTG_C2P_CLKN
differential pair DP_USB_SSTX2_C: +USB_SSTXP2_R -USB_SSTXN2_C
differential pair DP_USB_SSTX1_C: +USB_SSTXP1_C -USB_SSTXN1_C
differential pair DP_DISPLAYPORT_PS_SRC_AUX_C: +DISPLAYPORT_PS_SRC_AUX_P_C -DISPLAYPORT_PS_SRC_AUX_N_C
differential pair DP_DISPLAYPORT_PL_SRC_AUX_C: +"" -""
differential pair DP_B68_L14: +"" -""
differential pair DP_B68_L15: +"" -""
differential pair DP_B68_L16: +"" -""
differential pair DP_B68_L13: +"" -""
differential pair DP_B68_L3: +"" -""
differential pair DP_CLK3: +CLK3A -CLK3B
differential pair DP_QSFP2_TX4: +QSFP2_TX4P -QSFP2_TX4N
differential pair DP_SATA_TXB_C: +SATA_RXB+_C -SATA_RXB-_C
differential pair DP_SATA_TXB: +SATA_RXB+ -SATA_RXB-
differential pair DP_SATA_TXA_C: +SATA_TXA+_C -SATA_TXA-_C
differential pair DP_SATA_TXA: +SATA_TXA+ -SATA_TXA-
differential pair DP_QSFP2_TX3: +QSFP2_TX3P -QSFP2_TX3N
differential pair DP_QSFP2_TX2: +QSFP2_TX2P -QSFP2_TX2N
differential pair DP_QSFP2_TX1: +QSFP2_TX1P -QSFP2_TX1N
differential pair DP_QSFP2_RX4: +QSFP2_RX4P -QSFP2_RX4N
differential pair DP_QSFP2_RX3: +QSFP2_RX3P -QSFP2_RX3N
differential pair DP_QSFP2_RX2: +QSFP2_RX2P -QSFP2_RX2N
differential pair DP_QSFP2_RX1: +QSFP2_RX1P -QSFP2_RX1N
differential pair DP_QSFP1_TX4: +QSFP1_TX4P -QSFP1_TX4N
differential pair DP_QSFP1_TX3: +QSFP1_TX3P -QSFP1_TX3N
differential pair DP_QSFP1_TX2: +QSFP1_TX2P -QSFP1_TX2N
differential pair DP_QSFP1_RX4: +QSFP1_RX4P -QSFP1_RX4N
differential pair DP_QSFP1_RX3: +QSFP1_RX3P -QSFP1_RX3N
differential pair DP_QSFP1_RX2: +QSFP1_RX2P -QSFP1_RX2N
differential pair DP_QSFP1_TX1: +QSFP1_TX1P -QSFP1_TX1N
differential pair DP_QSFP1_RX1: +QSFP1_RX1P -QSFP1_RX1N
differential pair DP_PORTF_TX3: +SZG_PORTF_TX3P -SZG_PORTF_TX3N
differential pair DP_PORTF_TX2: +SZG_PORTF_TX2P -SZG_PORTF_TX2N
differential pair DP_PORTF_TX1: +SZG_PORTF_TX1P -SZG_PORTF_TX1N
differential pair DP_PORTF_TX0: +SZG_PORTF_TX0P -SZG_PORTF_TX0N
differential pair DP_PORTF_RX3: +SZG_PORTF_RX3P -SZG_PORTF_RX3N
differential pair DP_PORTF_RX2: +SZG_PORTF_RX2P -SZG_PORTF_RX2N
differential pair DP_PORTF_RX1: +SZG_PORTF_RX1P -SZG_PORTF_RX1N
differential pair DP_PORTF_RX0: +SZG_PORTF_RX0P -SZG_PORTF_RX0N
differential pair DP_PORTE_TX3: +SZG_PORTE_TX3P -SZG_PORTE_TX3N
differential pair DP_PORTF_REFCLK: +SZG_PORTF_REFCLKP -SZG_PORTF_REFCLKN
differential pair DP_PORTF_P2C_CLK: +SZG_PORTF_P2C_CLKP -SZG_PORTF_P2C_CLKN
differential pair DP_PORTF_C2P_CLK: +SZG_PORTF_C2P_CLKP -SZG_PORTF_C2P_CLKN
differential pair DP_PORTE_TX2: +SZG_PORTE_TX2P -SZG_PORTE_TX2N
differential pair DP_PORTE_TX1: +SZG_PORTE_TX1P -SZG_PORTE_TX1N
differential pair DP_PORTE_TX0: +SZG_PORTE_TX0P -SZG_PORTE_TX0N
differential pair DP_PORTE_RX3: +SZG_PORTE_RX3P -SZG_PORTE_RX3N
differential pair DP_PORTE_RX2: +SZG_PORTE_RX2P -SZG_PORTE_RX2N
differential pair DP_PORTE_RX1: +SZG_PORTE_RX1P -SZG_PORTE_RX1N
differential pair DP_PORTE_RX0: +SZG_PORTE_RX0P -SZG_PORTE_RX0N
differential pair DP_PORTE_REFCLK: +SZG_PORTE_REFCLKP -SZG_PORTE_REFCLKN
differential pair DP_PORTE_P2C_CLK: +SZG_PORTE_P2C_CLKP -SZG_PORTE_P2C_CLKN
differential pair DP_PORTE_C2P: +SZG_PORTE_C2P_CLKP -SZG_PORTE_C2P_CLKN
differential pair DP_PORTD_D7: +SZG_PORTD_S13_D7P -SZG_PORTD_S15_D7N
differential pair DP_PORTD_D6: +SZG_PORTD_S12_D6P -SZG_PORTD_S14_D6N
differential pair DP_PORTD_D5: +SZG_PORTD_S9_D5P -SZG_PORTD_S11_D5N
differential pair DP_PORTD_D4: +SZG_PORTD_S8_D4P -SZG_PORTD_S10_D4N
differential pair DP_PORTD_D3: +SZG_PORTD_S5_D3P -SZG_PORTD_S7_D3N
differential pair DP_PORTD_D2: +SZG_PORTD_S4_D2P -SZG_PORTD_S6_D2N
differential pair DP_PORTD_D1: +SZG_PORTD_S1_D1P -SZG_PORTD_S3_D1N
differential pair DP_PORTD_D0: +SZG_PORTD_S0_D0P -SZG_PORTD_S2_D0N
differential pair DP_PORTD_P2C_CLK: +SZG_PORTD_P2C_CLKP -SZG_PORTD_P2C_CLKN
differential pair DP_PORTD_C2P_CLK: +SZG_PORTD_C2P_CLKP -SZG_PORTD_C2P_CLKN
differential pair DP_PORTC_D7: +SZG_PORTC_S13_D7P -SZG_PORTC_S15_D7N
differential pair DP_PORTC_D6: +SZG_PORTC_S12_D6P -SZG_PORTC_S14_D6N
differential pair DP_PORTC_D5: +SZG_PORTC_S9_D5P -SZG_PORTC_S11_D5N
differential pair DP_PORTC_D4: +SZG_PORTC_S8_D4P -SZG_PORTC_S10_D4N
differential pair DP_PORTC_D3: +SZG_PORTC_S5_D3P -SZG_PORTC_S7_D3N
differential pair DP_PORTC_D2: +SZG_PORTC_S4_D2P -SZG_PORTC_S6_D2N
differential pair DP_PORTC_D1: +SZG_PORTC_S1_D1P -SZG_PORTC_S3_D1N
differential pair DP_PORTC_D0: +SZG_PORTC_S0_D0P -SZG_PORTC_S2_D0N
differential pair DP_PORTC_P2C_CLK: +SZG_PORTC_P2C_CLKP -SZG_PORTC_P2C_CLKN
differential pair DP_PORTC_C2P_CLK: +SZG_PORTC_C2P_CLKP -SZG_PORTC_C2P_CLKN
differential pair DP_PORTB_D7: +SZG_PORTB_S13_D7P -SZG_PORTB_S15_D7N
differential pair DP_PORTB_D6: +SZG_PORTB_S12_D6P -SZG_PORTB_S14_D6N
differential pair DP_PORTB_D5: +SZG_PORTB_S9_D5P -SZG_PORTB_S11_D5N
differential pair DP_PORTB_D4: +SZG_PORTB_S8_D4P -SZG_PORTB_S10_D4N
differential pair DP_PORTB_D3: +SZG_PORTB_S5_D3P -SZG_PORTB_S7_D3N
differential pair DP_PORTB_D2: +SZG_PORTB_S4_D2P -SZG_PORTB_S6_D2N
differential pair DP_PORTB_D1: +SZG_PORTB_S1_D1P -SZG_PORTB_S3_D1N
differential pair DP_PORTB_D0: +SZG_PORTB_S0_D0P -SZG_PORTB_S2_D0N
differential pair DP_PORTB_P2C_CLK: +SZG_PORTB_P2C_CLKP -SZG_PORTB_P2C_CLKN
differential pair DP_PORTB_C2P_CLK: +SZG_PORTB_C2P_CLKP -SZG_PORTB_C2P_CLKN
differential pair DP_ETH_TXRX_A_: +ETH_TXRX_A_P -ETH_TXRX_A_N
differential pair DP_ETH_TXRX_B_: +ETH_TXRX_B_P -ETH_TXRX_B_N
differential pair DP_ETH_TXRX_C_: +ETH_TXRX_C_P -ETH_TXRX_C_N
differential pair DP_ETH_TXRX_D_: +ETH_TXRX_D_P -ETH_TXRX_D_N
differential pair DP_USB_D: +USB_DP -USB_DN
differential pair DP_XADC_V: +XADC_VP -XADC_VN
differential pair DP_FPX1301_TX1_C: +"" -""
differential pair DP_FPX1301_TX1: +"" -""
differential pair DP_FPX1301_TX0_C: +"" -""
differential pair DP_FPX1301_TX0: +"" -""
differential pair DP_FPX1301_RX1_C: +"" -""
differential pair DP_FPX1301_RX1: +"" -""
differential pair DP_FPX1301_RX0_C: +"" -""
differential pair DP_FPX1301_RX0: +"" -""
differential pair DP_DISPLAYPORT_PS_SRC_LANE1_C: +"" -""
differential pair DP_DISPLAYPORT_PS_SRC_LANE1: +DISPLAYPORT_PS_SRC_LANE1_P -DISPLAYPORT_PS_SRC_LANE1_N
differential pair DP_DISPLAYPORT_PS_SRC_LANE0_C: +"" -""
differential pair DP_DISPLAYPORT_PS_SRC_LANE0: +DISPLAYPORT_PS_SRC_LANE0_P -DISPLAYPORT_PS_SRC_LANE0_N
differential pair DP_DISPLAYPORT_PS_SRC_CONN_LANE1_C: +"" -""
differential pair DP_DISPLAYPORT_PS_SRC_CONN_LANE1: +DISPLAYPORT_PS_SRC_CONN_LANE1_P -DISPLAYPORT_PS_SRC_CONN_LANE1_N
differential pair DP_DISPLAYPORT_PS_SRC_CONN_LANE0_C: +"" -""
differential pair DP_DISPLAYPORT_PS_SRC_CONN_LANE0: +DISPLAYPORT_PS_SRC_CONN_LANE0_P -DISPLAYPORT_PS_SRC_CONN_LANE0_N
differential pair DP_DISPLAYPORT_PS_SRC_AUX: +DISPLAYPORT_PS_SRC_AUX_P -DISPLAYPORT_PS_SRC_AUX_N
differential pair DP_DISPLAYPORT_PL_SRC_LANE1_N_C: +"" -""
differential pair DP_DISPLAYPORT_PL_SRC_LANE1: +"" -""
differential pair DP_DISPLAYPORT_PL_SRC_LANE0_C: +"" -""
differential pair DP_DISPLAYPORT_PL_SRC_LANE0: +"" -""
differential pair DP_DISPLAYPORT_PL_SRC_CONN_LANE1_C: +"" -""
differential pair DP_DISPLAYPORT_PL_SRC_CONN_LANE1: +"" -""
differential pair DP_DISPLAYPORT_PL_SRC_CONN_LANE0_C: +"" -""
differential pair DP_DISPLAYPORT_PL_SRC_CONN_LANE0: +"" -""
differential pair DP_DISPLAYPORT_PL_SRC_AUX: +"" -""
differential pair DP_DISPLAYPORT_PL_SNK_LANE1_C: +"" -""
differential pair DP_DISPLAYPORT_PL_SNK_LANE1: +"" -""
differential pair DP_DISPLAYPORT_PL_SNK_LANE0_C: +"" -""
differential pair DP_DISPLAYPORT_PL_SNK_LANE0: +"" -""
differential pair DP_DISPLAYPORT_PL_SNK_CONN_LANE1: +"" -""
differential pair DP_DISPLAYPORT_PL_SNK_CONN_LANE0: +"" -""
differential pair DP_DISPLAYPORT_PL_SNK_CONN_AUX_C: +"" -""
differential pair DP_DISPLAYPORT_PL_SNK_CONN_AUX: +"" -""
differential pair DP_DISPLAYPORT_PL_SNK_AUX_C: +"" -""
differential pair DP_DISPLAYPORT_PL_SNK_AUX: +"" -""
differential pair DP_CLK2: +CLK2A -CLK2B
differential pair DP_CLK1: +CLK1A -CLK1B
differential pair DP_CLK0: +CLK0A -CLK0B
differential pair DP_ETH_TXRX_A: +ETH_TXRX_A_P -ETH_TXRX_A_N
differential pair DP_ETH_TXRX_B: +ETH_TXRX_B_P -ETH_TXRX_B_N
differential pair DP_ETH_TXRX_C: +ETH_TXRX_C_P -ETH_TXRX_C_N
differential pair DP_ETH_TXRX_D: +ETH_TXRX_D_P -ETH_TXRX_D_N
differential pair DP_USB_SSTX2: +USB_SSTXP2 -USB_SSTXN2
differential pair DP_USB_SSTX1: +USB_SSTXP1 -USB_SSTXN1
differential pair DP_USB_SSTX_C: +"" -""
differential pair DP_USB_SSTX: +USB_SSTX_P -USB_SSTX_N
differential pair DP_USB_SSRX2: +USB_SSRXP2 -USB_SSRXN2
differential pair DP_USB_SSRX1: +USB_SSRXP1 -USB_SSRXN1
differential pair DP_USB_SSRX: +USB_SSRX_P -USB_SSRX_N

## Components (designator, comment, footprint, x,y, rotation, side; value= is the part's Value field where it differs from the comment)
*1 "Opal Kelly Logo" okLogo-23x5-2021 3018.36,940.25 r0 top
C1 "SM-0402, 10%, 10v" CAPC1005X06A#1 8700.79,5484.25 r180 top value="0.1 u"
C2 "C0402C104K8PACTU" CAPC1005X06A#2 7693,4930 r270 top value="0.1 u"
C3 "C0402C104K8PACTU" CAPC1005X06A#2 4347.05,858.27 r270 top value="0.1 u"
C4 "C0402C104K8PACTU" CAPC1005X06A#2 4346.46,716.14 r90 top value="0.1 u"
C5 "C0402C104K8PACTU" CAPC1005X06A#2 4494.18,946.91 r270 top value="0.1 u"
C6 "C0402C104K8PACTU" CAPC1005X06A#2 4458.74,946.91 r270 top value="0.1 u"
C7 "C0402C104K8PACTU" CAPC1005X06A#2 4606.3,858.27 r270 top value="0.1 u"
C8 "C0402C104K8PACTU" CAPC1005X06A#2 4606.3,716.54 r90 top value="0.1 u"
C9 "JMK105BBJ475MV-F" CAPC1005X06A#2 8178.76,3860.25 r90 top value=4.7u
C10 "C0402C104K8PACTU" CAPC1005X06A#2 8214.19,3860.25 r90 top value="0.1 u"
C11 "C0402C104K8PACTU" CAPC1005X06A#2 8426.79,4111.83 r90 top value="0.1 u"
C12 "C0402C104K8PACTU" CAPC1005X06A#2 8631.51,4107.89 r90 top value="0.1 u"
C13 "JMK105BBJ475MV-F" CAPC1005X06A#2 8072.46,3861.83 r90 top value=4.7u
C14 "C0402C104K8PACTU" CAPC1005X06A#2 8107.89,3862.22 r90 top value="0.1 u"
C15 "C0402C104K8PACTU" CAPC1005X06A#2 8359.86,4237.81 r270 top value="0.1 u"
C16 "C0402C104K8PACTU" CAPC1005X06A#2 8265.37,3860.25 r90 top value="0.1 u"
C17 "C0402C104K8PACTU" CAPC1005X06A#2 7930.72,4037.02 r0 top value="0.1 u"
C18 "C0402C103K4RACTU" CAPC1005X06A#2 7816.55,4100.01 r180 top value="0.01 u"
C19 "JMK105BBJ475MV-F" CAPC1005X06A#2 7922.85,4103.95 r0 top value=4.7u
C20 "TMK105BJ104KV-F" CAPC1005X06A#1 2380,3958 r180 top value="0.1 u"
C21 "TMK105BJ104KV-F" CAPC1005X06A#1 2822.08,3957 r0 top value="0.1 u"
C22 "C0402C104K8PACTU" CAPC1005X06A#2 7922.85,4139.39 r0 top value="0.1 u"
C23 "JMK105BBJ475MV-F" CAPC1005X06A#2 7867.73,4218.13 r270 top value=4.7u
C24 "SM-0402, 10%, 10v" CAPC1005X06A#1 926,364.08 r90 top value="0.1 u"
C25 "SM-0402, 10%, 10v" CAPC1005X06A#1 890,364 r90 top value="0.1 u"
C26 "SM-0402, 10%, 10v" CAPC1005X06A#1 775.15,364 r90 top value="0.1 u"
C27 "SM-0402, 10%, 10v" CAPC1005X06A#1 739.15,364 r90 top value="0.1 u"
C28 "C0402C104K8PACTU" CAPC1005X06A#2 7922.85,4174.82 r0 top value="0.1 u"
C29 "C0402C104K8PACTU" CAPC1005X06A#2 8426.79,3832.69 r90 top value="0.1 u"
C30 "C0402C104K8PACTU" CAPC1005X06A#2 8631.51,3832.3 r90 top value="0.1 u"
C31 "C0402C104K8PACTU" CAPC1005X06A#2 7922.85,4225.01 r0 top value="0.1 u"
C32 "C0402C104K8PACTU" CAPC1005X06A#2 7922.85,4260.45 r0 top value="0.1 u"
C33 "C0402C104K8PACTU" CAPC1005X06A#2 8426.79,3970.49 r90 top value="0.1 u"
C34 "C0402C104K8PACTU" CAPC1005X06A#2 8631.51,3970.09 r90 top value="0.1 u"
C35 "C0402C103K4RACTU" CAPC1005X06A#2 8139.39,4316.55 r180 top value="0.01 u"
C36 "SM-0402, 10%, 10v" CAPC1005X06A#2 7238.57,4021.28 r90 top value="0.1 u"
C37 "C0402C180J5GACTU" CAPC1005X06A#2 7930.72,3938.6 r0 top value="18 p"
C38 "C0402C180J5GACTU" CAPC1005X06A#2 8056.71,3775.21 r90 top value="18 p"
C39 "C0402C104K8PACTU" CAPC1005X06A#2 8422.85,4245.68 r90 top value="0.1 u"
C40 "C0402C104K8PACTU" CAPC1005X06A#2 8631.51,4245.68 r90 top value="0.1 u"
C41 "C0402C104K8PACTU" CAPC1005X06A#2 7848.05,3781.12 r0 top value="0.1 u"
C42 "JMK105BBJ475MV-F" CAPC1005X06A#2 8155.13,3763.4 r270 top value=4.7u
C49 "C0402C104K8PACTU" CAPC1005X06A#1 6769.9,4685.95 r0 top value="0.1 u"
C50 "C0402C104K8PACTU" CAPC1005X06A#2 6839.9,4567.95 r270 top value="0.1 u"
C51 "SM-1206, 10%, 10v, X7R" CAPC3216N 6479.33,3666.34 r0 top value=22u
C52 "SM-0402, 10%, 10v" CAPC1005X06A#2 6776.57,3638.78 r180 top value="0.1 u"
C53 "SM-0402, 10%, 10v" CAPC1005X06A#1 6532.48,3457.68 r0 top value="0.1 u"
C54 "SM-1206, 10%, 10v, X7R" CAPC3216N 6575.79,3337.6 r90 top value=22u
C55 "SM-0402, 10%, 10v" CAPC1005X06A#1 6671.26,3457.68 r0 top value="0.1 u"
C56 "SM-1206, 10%, 10v, X7R" CAPC3216N 6714.57,3337.6 r90 top value=22u
C57 "SM-0402, 10%, 10v" CAPC1005X06A#1 6415.56,3457.68 r0 top value="0.1 u"
C58 "SM-1206, 10%, 10v, X7R" CAPC3216N 6433.07,3337.6 r90 top value=22u
C59 "C0402C104K8PACTU" CAPC1005X06A#1 6646.94,4079.54 r90 top value="0.1 u"
C60 "C0402C104K8PACTU" CAPC1005X06A#1 6646.94,3882.69 r90 top value="0.1 u"
C61 "LMK105BJ105KV-F" CAPC1005X06A#1 6646.94,3961.43 r270 top value=1u
C62 "C0402C104K8PACTU" CAPC1005X06A#2 6647.22,4691.74 r90 top value="0.1 u"
C63 "C0402C104K8PACTU" CAPC1005X06A#1 6647.22,4494.89 r90 top value="0.1 u"
C64 "LMK105BJ105KV-F" CAPC1005X06A#2 6647.22,4573.63 r270 top value=1u
C65 "C0402C104K8PACTU" CAPC1005X06A#1 7312.02,4989.67 r0 top value="0.1 u"
C66 "C0402C104K8PACTU" CAPC1005X06A#2 7380.02,4873.67 r270 top value="0.1 u"
C67 "SM-1206, 10%, 10v, X7R" CAPC3216N 6479.33,2603.35 r0 top value=22u
C68 "SM-0402, 10%, 10v" CAPC1005X06A#1 6776.57,2575.79 r180 top value="0.1 u"
C69 "C0402C104K8PACTU" CAPC1005X06A#2 5685.04,5535.43 r0 top value="0.1 u"
C70 "C0402C104K8PACTU" CAPC1005X06A#1 5803.15,5425.2 r270 top value="0.1 u"
C71 "C0402C104K8PACTU" CAPC1005X06A#1 5668.02,4856.28 r0 top value="0.1 u"
C72 "C0402C104K8PACTU" CAPC1005X06A#1 5668.02,4815.28 r0 top value="0.1 u"
C73 "CL05A225KQ5NNNC" CAPC1005X06A#1 5836.02,5010.28 r270 top value="2.2 u"
C74 "C0402C104K8PACTU" CAPC1005X06A#1 5668.02,4774.28 r0 top value="0.1 u"
C75 "C0402C104K8PACTU" CAPC1005X06A#1 6161.35,5180 r90 top value="0.1 u"
C76 "C0402C104K8PACTU" CAPC1005X06A#1 5967.41,5288.32 r270 top value="0.1 u"
C77 "C0402C120J5GACTU" CAPC1005X06A#1 5650.02,4919.28 r270 top value="12 p"
C78 "C0402C120J5GACTU" CAPC1005X06A#1 5650.02,4994.28 r270 top value="12 p"
C79 "C0402C104K8PACTU" CAPC1005X06A#1 6158,5435 r90 top value="0.1 u"
C80 "C0402C104K8PACTU" CAPC1005X06A#1 6194,5435 r90 top value="0.1 u"
C81 "C0402C104K8PACTU" CAPC1005X06A#1 5824,5596 r0 top value="0.1 u"
C82 "EMK212BJ106KG-T" CAPC2012X14N 4230.32,5790.94 r0 top value=10u
C83 "C0402C103K4RACTU" CAPC1005X06A#2 4236.61,5570.47 r0 top value="0.01 u"
C84 "C0402C103K4RACTU" CAPC1005X06A#2 4293.31,5637.4 r270 top value="0.01 u"
C85 "EMK212BJ106KG-T" CAPC2012X14N 4356.3,5637.4 r270 top value=10u
C86 "EMK212BJ106KG-T" CAPC2012X14N 4576.77,5790.94 r0 top value=10u
C87 "C0402C103K4RACTU" CAPC1005X06A#2 4584.65,5570.47 r0 top value="0.01 u"
C88 "C0402C103K4RACTU" CAPC1005X06A#2 4639.76,5637.4 r270 top value="0.01 u"
C89 "EMK212BJ106KG-T" CAPC2012X14N 4702.76,5637.4 r270 top value=10u
C90 "LMK105BJ105KV-F" CAPC1005X06A#2 4443.51,4650.43 r90 top value=1u
C91 "C0402C104K8PACTU" CAPC1005X06A#2 4408.08,4650.82 r90 top value="0.1 u"
C92 "LMK105BJ105KV-F" CAPC1005X06A#2 3940.94,4996.06 r0 top value=1u
C93 "C0402C104K8PACTU" CAPC1005X06A#2 4015.75,4996.06 r0 top value="0.1 u"
C94 "C0402C104K8PACTU" CAPC1005X06A#1 7693,5178 r270 top value="0.1 u"
C95 "LMK105BJ105KV-F" CAPC1005X06A#2 4283.46,5326.77 r270 top value=1u
C96 "C0402C104K8PACTU" CAPC1005X06A#2 4248.03,5326.77 r270 top value="0.1 u"
C97 "LMK105BJ105KV-F" CAPC1005X06A#2 4755.91,4988.19 r180 top value=1u
C98 "C0402C104K8PACTU" CAPC1005X06A#2 4677.56,4988.19 r180 top value="0.1 u"
C99 "EMK212BJ106KG-T" CAPC2012X14N 4098.43,5267.72 r270 top value=10u
C100 "C0402C103K4RACTU" CAPC1005X06A#2 4157.48,5287.4 r270 top value="0.01 u"
C101 "LMK105BJ105KV-F" CAPC1005X06A#2 4337.21,4650.82 r90 top value=1u
C102 "C0402C104K8PACTU" CAPC1005X06A#2 4372.65,4650.82 r90 top value="0.1 u"
C103 "C0402C104K8PACTU" CAPC1005X06A#2 4693.31,4897.64 r180 top value="0.1 u"
C104 "LMK105BJ105KV-F" CAPC1005X06A#2 4771.65,4897.64 r180 top value=1u
C105 "LMK105BJ105KV-F" CAPC1005X06A#2 3940.94,5031.5 r0 top value=1u
C106 "C0402C104K8PACTU" CAPC1005X06A#1 4015.75,5031.5 r0 top value="0.1 u"
C107 "C0402C104K8PACTU" CAPC1005X06A#1 4677.56,5066.93 r180 top value="0.1 u"
C108 "LMK105BJ105KV-F" CAPC1005X06A#1 4735.83,5087.01 r270 top value=1u
C109 "LMK105BJ105KV-F" CAPC1005X06A#1 4401.57,5385.83 r270 top value=1u
C110 "C0402C104K8PACTU" CAPC1005X06A#2 4401.57,5307.09 r270 top value="0.1 u"
C111 "TMK105BJ104KV-F" CAPC1005X06A#2 5363,4951 r90 top value="0.1 u"
C112 "TMK105BJ104KV-F" CAPC1005X06A#2 5326,4951 r90 top value="0.1 u"
C113 "LMK107BJ106MALTD" CAPC1608X09N 1394,4055 r270 top value=10u
C114 "JMK105BBJ475MV-F" CAPC1005X06A#1 1345.99,4039.64 r270 top value=4.7u
C115 "C1005X5R1A335K050BC" CAPC1005X06A#1 1310.58,4027.64 r270 top value=3.3u
C116 "C3216X5R1V226M160AC" CAPC3216N 1273,4160 r90 top value="22 u"
C117 "TMK105BJ104KV-F" CAPC1005X06A#1 1256,4016 r180 top value="0.1 u"
C118 "C0402C104K8PACTU" CAPC1005X06A#1 1539.58,3689.64 r0 top value="0.1 u"
C119 "C0402C104K8PACTU" CAPC1005X06A#1 1862.58,3732.64 r270 top value="0.1 u"
C120 "LMK316AB7226KL-TR" CAPC3216N 1706.58,3735.64 r270 top value=22u
C121 "LMK316AB7226KL-TR" CAPC3216N 1797.58,3735.64 r270 top value=22u
C122 "SM-0402, 5%, 50v" CAPC1005X06A#1 1523.58,3632.64 r270 top value="56 p"
C123 "C0402C472K5RACTU" CAPC1005X06A#1 1439.66,3560.64 r270 top value="4.7 n"
C124 "C0402C104K8PACTU" CAPC1005X06A#1 1368,3612 r270 top value="0.1 u"
C125 "C0402C220J5GACTU" CAPC1005X06A#1 1403.58,3560.56 r270 top value="22 p"
C126 "C0402C104K8PACTU" CAPC1005X06A#1 1539.58,3980.64 r0 top value="0.1 u"
C127 "C3216X5R1V226M160AC" CAPC3216N 1583.58,3827.64 r90 top value="22 u"
C128 "TMK105BJ104KV-F" CAPC1005X06A#1 1519.58,3827.64 r90 top value="0.1 u"
C129 "C0402C104K8PACTU" CAPC1005X06A#1 1861.58,3917.64 r90 top value="0.1 u"
C130 "LMK316AB7226KL-TR" CAPC3216N 1706.58,3920.64 r90 top value=22u
C131 "LMK316AB7226KL-TR" CAPC3216N 1797.58,3920.64 r90 top value=22u
C132 "C0402C104K8PACTU" CAPC1005X06A#1 1480,4179 r270 top value="0.1 u"
C133 "SM-0402, 5%, 50v" CAPC1005X06A#1 1529,4105 r90 top value="56 p"
C134 "EEE-FK1E221P" CAPAE9083X70N 875,5033 r0 top value=220u
C135 "TMK105BJ104KV-F" CAPC1005X06A#1 648,5207 r270 top value="0.1 u"
C136 "C0402C472K5RACTU" CAPC1005X06A#1 1443,4203 r90 top value="4.7 n"
C137 "C0402C220J5GACTU" CAPC1005X06A#1 1456,4058 r90 top value="22 p"
C138 "C0402C104K8PACTU" CAPC1005X06A#1 1166,4132 r90 top value="0.1 u"
C139 "C0402C104K8PACTU" CAPC1005X06A#1 1061.58,3932.64 r270 top value="0.1 u"
C140 "C3216X5R1V226M160AC" CAPC3216N 1060,3811 r180 top value="22 u"
C141 "TMK105BJ104KV-F" CAPC1005X06A#1 1112,3874 r180 top value="0.1 u"
C142 "C0402C104K8PACTU" CAPC1005X06A#1 645.58,3893.64 r90 top value="0.1 u"
C143 "LMK316AB7226KL-TR" CAPC3216N 854.36,3862.58 r180 top value=22u
C144 "LMK316AB7226KL-TR" CAPC3216N 708.58,3911.64 r90 top value=22u
C145 "C0402C560J5GACTU" CAPC1005X06A#1 1095.8,4005.47 r90 top value="56 p"
C146 "C0402C104K8PACTU" CAPC1005X06A#1 1241.29,3609.53 r270 top value="0.1 u"
C147 "C0402C472K5RACTU" CAPC1005X06A#1 1203,4100 r90 top value="4.7 n"
C148 "C0402C220J5GACTU" CAPC1005X06A#1 1167,4056 r90 top value="22 p"
C149 "C0402C104K8PACTU" CAPC1005X06A#1 1061.58,3726.64 r90 top value="0.1 u"
C150 "C0402C104K8PACTU" CAPC1005X06A#1 645.58,3742.72 r270 top value="0.1 u"
C151 "LMK316AB7226KL-TR" CAPC3216N 854.53,3768.42 r180 top value=22u
C152 "LMK316AB7226KL-TR" CAPC3216N 708.58,3725.64 r270 top value=22u
C153 "C0402C560J5GACTU" CAPC1005X06A#1 1095,3649 r270 top value="56 p"
C154 "SM-0402, 5%, 50V, NP0" CAPC1005X06A#1 1277.4,3538.16 r90 top value="100 p"
C155 "C0402C472K5RACTU" CAPC1005X06A#1 1189.29,3550.53 r0 top value="4.7 n"
C156 "GJM1555C1H5R0CB01D" CAPC1005X06A#1 1313.4,3538.16 r90 top value="5 p"
C157 "C0402C220J5GACTU" CAPC1005X06A#1 1204.58,3621.64 r270 top value="22 p"
C159 "TMK105BJ104KV-F" CAPC1005X06A#2 5010,4951 r90 top value="0.1 u"
C163 "TMK105BJ104KV-F" CAPC1005X06A#1 4973,4951 r90 top value="0.1 u"
C164 "GR443DR73D472KW01L" CC4532-1812 5641.73,5795.28 r180 top value="4700 p"
C168 "C0402C330J5GACTU" CAPC1005X06A#1 4622.05,5444.88 r0 top value="33 p"
C170 "SM-0402, 10%, 10v" CAPC1005X06A#1 1735.53,978 r90 top value="0.1 u"
C171 "SM-0402, 10%, 10v" CAPC1005X06A#1 1698.53,978 r90 top value="0.1 u"
C174 "C0402C104K8PACTU" CAPC1005X06A#1 6057,5435 r90 top value="0.1 u"
C175 "C0402C104K8PACTU" CAPC1005X06A#1 6093,5435 r90 top value="0.1 u"
C178 "SM-0402, 10%, 10v" CAPC1005X06A#2 6532.48,2394.68 r0 top value="0.1 u"
C179 "SM-1206, 10%, 10v, X7R" CAPC3216N 6575.79,2274.61 r90 top value=22u
C180 "SM-0402, 10%, 10v" CAPC1005X06A#2 6671.26,2394.68 r0 top value="0.1 u"
C181 "SM-1206, 10%, 10v, X7R" CAPC3216N 6714.57,2274.61 r90 top value=22u
C182 "SM-0402, 10%, 10v" CAPC1005X06A#1 1913.09,979 r90 top value="0.1 u"
C183 "SM-0402, 10%, 10v" CAPC1005X06A#1 1574.53,641 r270 top value="0.1 u"
C184 "SM-0402, 10%, 10v" CAPC1005X06A#2 6415.56,2394.68 r0 top value="0.1 u"
C185 "SM-0402, 10%, 10v" CAPC1005X06A#1 1877.09,979 r90 top value="0.1 u"
C186 "SM-1206, 10%, 10v, X7R" CAPC3216N 6433.07,2274.61 r90 top value=22u
C187 "SM-0402, 10%, 10v" CAPC1005X06A#1 1841.09,979 r90 top value="0.1 u"
C188 "C0402C104K8PACTU" CAPC1005X06A#2 6750.19,5019.68 r180 top value="0.1 u"
C189 "SM-0402, 10%, 10v" CAPC1005X06A#1 1805.09,979 r90 top value="0.1 u"
C190 "C0402C103K4RACTU" CAPC1005X06A#1 2172,416 r180 top value="0.01 u"
C212 "C0402C104K8PACTU" CAPC1005X06A#2 6947.04,5019.68 r180 top value="0.1 u"
C213 "LMK105BJ105KV-F" CAPC1005X06A#2 6868.3,5019.68 r0 top value=1u
C214 "C0402C330J5GACTU" CAPC1005X06A#2 4720.47,5322.83 r90 top value="33 p"
C215 "LMK212BJ106KG-T" CAPC2012X14N 4787.4,4653.54 r270 top value=10u
C218 "C0402C104K8PACTU" CAPC1005X06A#2 2196.85,996.46 r90 top value="0.1 u"
C219 "C0402C104K8PACTU" CAPC1005X06A#2 2377.95,996.46 r90 top value="0.1 u"
C220 "LMK107BJ106MALTD" CAPC1608X09N 5653.54,5586.61 r0 top value=10u
C221 "GRM31CR60J157ME11L" CAPC3216N 6342.52,5421.26 r90 top value="150 u"
D1 "VBUS_FAULT" CD1608-0603-PIN1-CATHODE 5770,5180 r180 top
D2 "Diode" SOD-123 4921.2,4628.25 r0 top
D3 "Diode" SOD-123 4921.2,4709.25 r0 top
D4 "POWER" CD1608-0603-PIN1-CATHODE 1100,4683 r0 top
D5 "D5V0FS4U10LP-7" D5V0FS4U10LP 7552.77,4026.39 r180 top
FB1 "BLM21PG221SN1D" RESC2012N 5794,5653 r180 top value=220
FB2 "MI0603J601R-10" INDC1608X06N 8202.38,3763.79 r90 top value=600
FB3 "MI0603J601R-10" INDC1608X06N 8107.89,3763.79 r90 top value=600
FB4 "MI0603J601R-10" INDC1608X06N 7832.3,4147.26 r180 top value=600
FB5 "BLM21PG221SN1D" RESC2012N 7297.62,3989.78 r270 top value=220
FID1 "FIDUCIAL" FID1MM/2MM-SS 368,5559 r90 top
FID2 "FIDUCIAL" FID1MM/2MM-SS 8291.17,5499.32 r90 top
FID3 "FIDUCIAL" FID1MM/2MM-SS 8632.5,465.91 r90 top
FID4 "FIDUCIAL" FID1MM/2MM-SS 348,337 r90 top
FID5 "FIDUCIAL" FID1MM/2MM-SS 2393.7,4496.06 r90 bottom
FID6 "FIDUCIAL" FID1MM/2MM-SS 8291.17,5499.32 r90 bottom
FID7 "FIDUCIAL" FID1MM/2MM-SS 8632.5,465.91 r90 bottom
FID8 "FIDUCIAL" FID1MM/2MM-SS 348,337 r90 bottom
J1 "QSE-020-01-F-D-A" QSE-020-01-X-D-A-L-SYZYGY 3189.03,5708.66 r180 top locked
J2 "87831-1420" XILINX-JTAG 8515.39,5167 r270 top
J3 "0877584016" HDR2X20-2MM 2755.91,5039.37 r0 top
J4 "0877582016" HDR2X10-2MM 7283.46,5511.81 r0 top
J5 "QSH-020-01-F-D-DP-A" QSH-020-01-X-D-DP-A-L-SYZYGY 7405.07,196.85 r0 top locked
J6 "QSH-020-01-F-D-DP-A" QSH-020-01-X-D-DP-A-L-SYZYGY 3310.58,196.85 r0 top locked
J7 "QSH-020-01-F-D-DP-A" QSH-020-01-X-D-DP-A-L-SYZYGY 5357.82,196.85 r0 top locked
J8 "QSE-020-01-F-D-A" QSE-020-01-X-D-A-L-SYZYGY 196.85,1299.26 r270 top locked
J9 "QSE-020-01-F-D-A" QSE-020-01-X-D-A-L-SYZYGY 196.85,3149.66 r270 top locked
J10 "087758-1216" HDR2X6-2MM 1081.63,2751.37 r90 top
J11 "QSE-020-01-F-D-A" QSE-020-01-X-D-A-L-SYZYGY 1338.63,5708.66 r180 top locked
J12 "67800-5005" MOLEX-67800-5005 826.77,196.85 r0 top locked
J13 "PBC03SAAN" HDR1X3 7775.59,4704.72 r0 top
J14 "FS1-Z38-20Z6-60" QSFP28_RECEPTACLE_SFF-8679 7401.59,2698.92 r90 top locked
J15 "FS1-Z38-20Z6-60" QSFP28_RECEPTACLE_SFF-8679 7401.58,1635.91 r90 top locked
J16 "1054500101" 1054500101 6268.5,5623.23 r180 top locked
J17 "L829-1J1T-43" L829-1J1T-43 5126,5462.6 r180 top locked
J18 "PJ-102AH" CUI-PJ102A -86.61,5140 r270 top locked
J19 "0455580003" 0455580003 460.63,4506.34 r90 top locked
J20 "0472720001" 0472720001 1732.28,129.92 r0 top locked
J21 "USB4120-03-C" USB4120-03-C 7552.77,4183.87 r180 top
JSO1 "Jack Screw Standoff" JSO-0515-01 2598.42,4389.76 r0 top locked
JSO2 "Jack Screw Standoff" JSO-0515-01 5511.81,4389.76 r0 top locked
JSO3 "Jack Screw Standoff" JSO-0515-01 2598.42,1515.75 r0 top locked
JSO4 "Jack Screw Standoff" JSO-0515-01 5511.81,1515.75 r0 top locked
L1 "XAL6030-222MEB" XAL60XX 1692.58,3503.64 r0 top value=2.2u
L2 "XAL6030-222MEB" XAL60XX 1692.58,4152.64 r0 top value=2.2u
L3 "VLS4012CX-2R2M-1" VLS4012CX 901.57,4007.87 r180 top value=2.2u
L4 "VLS4012CX-2R2M-1" VLS4012CX 901.57,3622.05 r180 top value=2.2u
L5 "CIGT252010LM1R0MNE" CIGT252010 6579.72,3552.17 r270 top value=1u
L6 "CIGT252010LM1R0MNE" CIGT252010 6718.5,3552.17 r270 top value=1u
L7 "CIGT252010LM1R0MNE" CIGT252010 6435.04,3552.17 r270 top value=1u
L8 "CIGT252010LM1R0MNE" CIGT252010 6579.72,2489.17 r270 top value=1u
L9 "CIGT252010LM1R0MNE" CIGT252010 6718.5,2489.17 r270 top value=1u
L10 "CIGT252010LM1R0MNE" CIGT252010 6435.04,2489.17 r270 top value=1u
MC1 "QTH-060-01-F-D-A" QTH-060-01-X-D 3661.42,4389.76 r0 top locked
MC2 "QTH-060-01-L-D-DP-A" QTH-060-01-X-D-DP-A 4055.12,1515.75 r0 top locked
MC3 "QTH-090-01-F-D-A" QTH-090-01-X-D 2598.42,2952.76 r90 top locked
MH1 "MTG" MTG-3.2/6.5-PTH 196.85,5708.66 r0 top locked
MH2 "MTG" MTG-3.2/6.5-PTH 8661.42,5708.66 r0 top locked
MH3 "MTG" MTG-3.2/6.5-PTH 8661.42,196.85 r0 top locked
MH4 "MTG" MTG-3.2/6.5-PTH 196.85,196.85 r0 top locked
MH5 "MTG" MTG-3.2/6.5-PTH 4055.12,2952.76 r0 top locked
Q1 "2.2A, 30V" SOT23-95P240X110 1065.7,4516.67 r0 top
Q2 "SI1922EDH-T1-GE3" SOT363-6N 5188.98,4740.16 r0 top
Q3 "SI1922EDH-T1-GE3" SOT363-6N 5188.98,4641.73 r0 top
QSFP1 "Pressfit" QSFP28_SINGLE_CAGE 7401.59,2698.92 r90 top locked
QSFP2 "Pressfit" QSFP28_SINGLE_CAGE 7401.58,1635.91 r90 top locked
